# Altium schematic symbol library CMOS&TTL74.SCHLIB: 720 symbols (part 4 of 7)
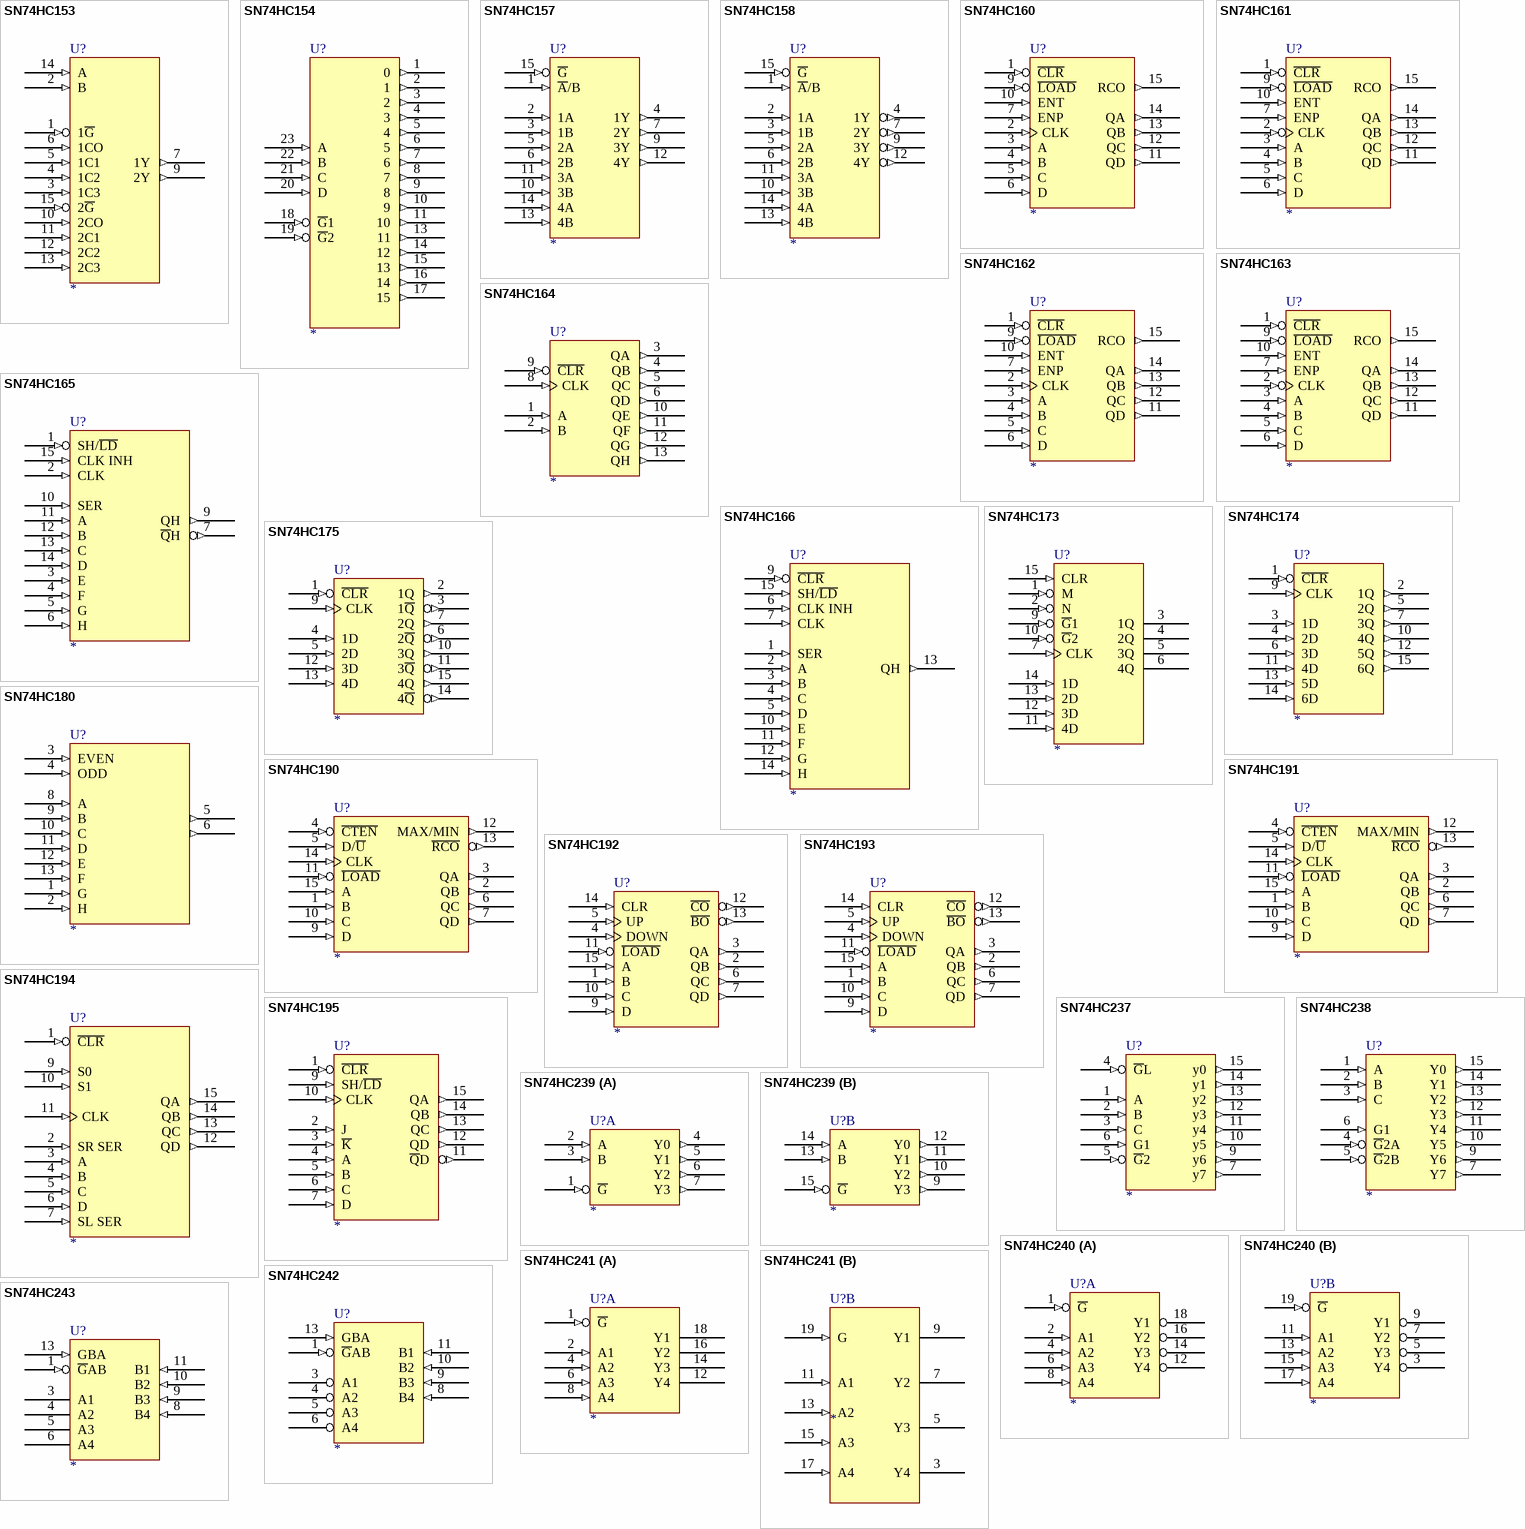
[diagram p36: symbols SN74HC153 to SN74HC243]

## SN74HC160
designator U?
SYN 4-BIT CNT
footprint SO16
footprint DIP-16
pins: 1 ~{CLR} (in), 2 CLK (in), 3 A (in), 4 B (in), 5 C (in), 6 D (in), 7 ENP (in), 8 GND (power) hidden to GND, 9 ~{LOAD} (in), 10 ENT (in), 11 QD (out), 12 QC (out), 13 QB (out), 14 QA (out), 15 RCO (out), 16 VCC (power) hidden to VCC
1 alternate drawing of the same symbol

## SN74HC161
designator U?
SYN 4-BIT CNT
footprint SO16
footprint DIP-16
pins: 1 ~{CLR} (in), 2 CLK (in), 3 A (in), 4 B (in), 5 C (in), 6 D (in), 7 ENP (in), 8 GND (power) hidden to GND, 9 ~{LOAD} (in), 10 ENT (in), 11 QD (out), 12 QC (out), 13 QB (out), 14 QA (out), 15 RCO (out), 16 VCC (power) hidden to VCC
1 alternate drawing of the same symbol

## SN74HC162
designator U?
SYN 4-BIT CNT
footprint SO16
footprint DIP-16
pins: 1 ~{CLR} (in), 2 CLK (in), 3 A (in), 4 B (in), 5 C (in), 6 D (in), 7 ENP (in), 8 GND (power) hidden to GND, 9 ~{LOAD} (in), 10 ENT (in), 11 QD (out), 12 QC (out), 13 QB (out), 14 QA (out), 15 RCO (out), 16 VCC (power) hidden to VCC
1 alternate drawing of the same symbol

## SN74HC163
designator U?
SYN 4-BIT CNT
footprint SO16
footprint DIP-16
pins: 1 ~{CLR} (in), 2 CLK (in), 3 A (in), 4 B (in), 5 C (in), 6 D (in), 7 ENP (in), 8 GND (power) hidden to GND, 9 ~{LOAD} (in), 10 ENT (in), 11 QD (out), 12 QC (out), 13 QB (out), 14 QA (out), 15 RCO (out), 16 VCC (power) hidden to VCC
1 alternate drawing of the same symbol

## SN74HC164
designator U?
8-BIT PALL SERI SFT REG
footprint DIP-14
pins: 1 A (in), 2 B (in), 3 QA (out), 4 QB (out), 5 QC (out), 6 QD (out), 7 GND (power) hidden to GND, 8 CLK (in), 9 ~{CLR} (in), 10 QE (out), 11 QF (out), 12 QG (out), 13 QH (out), 14 VCC (power) hidden to VCC
1 alternate drawing of the same symbol

## SN74HC165
designator U?
PALL LOAD 8-BIT SFT REG
footprint SO16
footprint DIP-16
pins: 1 SH/~{LD} (in), 2 CLK (in), 3 E (in), 4 F (in), 5 G (in), 6 H (in), 7 ~{Q}H (out), 8 GND (power) hidden to GND, 9 QH (out), 10 SER (in), 11 A (in), 12 B (in), 13 C (in), 14 D (in), 15 CLK INH (in), 16 VCC (power) hidden to VCC
1 alternate drawing of the same symbol

## SN74HC166
designator U?
PALL LOAD 8-BIT SFT REG
footprint SO16
footprint DIP-16
pins: 1 SER (in), 2 A (in), 3 B (in), 4 C (in), 5 D (in), 6 CLK INH (in), 7 CLK (in), 8 GND (power) hidden to GND, 9 ~{CLR} (in), 10 E (in), 11 F (in), 12 G (in), 13 QH (out), 14 H (in), 15 SH/~{LD} (in), 16 VCC (power) hidden to VCC
1 alternate drawing of the same symbol

## SN74HC173
designator U?
4-BIT D-TYPE REG 3SO
footprint SO16
footprint DIP-16
pins: 1 M (in), 2 N (in), 3 1Q (hiz), 4 2Q (hiz), 5 3Q (hiz), 6 4Q (hiz), 7 CLK (in), 8 GND (power) hidden to GND, 9 ~{G}1 (in), 10 ~{G}2 (in), 11 4D (in), 12 3D (in), 13 2D (in), 14 1D (in), 15 CLR (in), 16 VCC (power) hidden to VCC
1 alternate drawing of the same symbol

## SN74HC174
designator U?
HEX D-TYPE FF CR
footprint SO16
footprint DIP-16
pins: 1 ~{CLR} (in), 2 1Q (out), 3 1D (in), 4 2D (in), 5 2Q (out), 6 3D (in), 7 3Q (out), 8 GND (power) hidden to GND, 9 CLK (in), 10 4Q (out), 11 4D (in), 12 5Q (out), 13 5D (in), 14 6D (in), 15 6Q (out), 16 VCC (power) hidden to VCC
1 alternate drawing of the same symbol

## SN74HC175
designator U?
QUAD D-TYPE FF CR
footprint SO16
footprint DIP-16
pins: 1 ~{CLR} (in), 2 1Q (out), 3 1~{Q} (out), 4 1D (in), 5 2D (in), 6 2~{Q} (out), 7 2Q (out), 8 GND (power) hidden to GND, 9 CLK (in), 10 3Q (out), 11 3~{Q} (out), 12 3D (in), 13 4D (in), 14 4~{Q} (out), 15 4Q (out), 16 VCC (power) hidden to VCC
1 alternate drawing of the same symbol

## SN74HC180
designator U?
9-BIT PARITY GNR/CHKR
footprint SO14
footprint DIP-14
pins: 1 G (in), 2 H (in), 3 EVEN (in), 4 ODD (in), 5 (out), 6 (out), 7 GND (power) hidden to GND, 8 A (in), 9 B (in), 10 C (in), 11 D (in), 12 E (in), 13 F (in), 14 VCC (power) hidden to VCC
1 alternate drawing of the same symbol

## SN74HC190
designator U?
SYN UP/DOWN CNT DOWN/UP MODE CONTTOL
footprint SO16
footprint DIP-16
pins: 1 B (in), 2 QB (out), 3 QA (out), 4 ~{CTEN} (in), 5 D/~{U} (in), 6 QC (out), 7 QD (out), 8 GND (power) hidden to GND, 9 D (in), 10 C (in), 11 ~{LOAD} (in), 12 MAX/MIN (out), 13 ~{RCO} (out), 14 CLK (in), 15 A (in), 16 VCC (power) hidden to VCC
1 alternate drawing of the same symbol

## SN74HC191
designator U?
SYN UP/DOWN CNT DOWN/UP MODE CONTTOL
footprint SO16
footprint DIP-16
pins: 1 B (in), 2 QB (out), 3 QA (out), 4 ~{CTEN} (in), 5 D/~{U} (in), 6 QC (out), 7 QD (out), 8 GND (power) hidden to GND, 9 D (in), 10 C (in), 11 ~{LOAD} (in), 12 MAX/MIN (out), 13 ~{RCO} (out), 14 CLK (in), 15 A (in), 16 VCC (power) hidden to VCC
1 alternate drawing of the same symbol

## SN74HC192
designator U?
SYN 4-BIT UP/DOWN CNT DUAL CLK CR
footprint SO16
footprint DIP-16
pins: 1 B (in), 2 QB (out), 3 QA (out), 4 DOWN (in), 5 UP (in), 6 QC (out), 7 QD (out), 8 GND (power) hidden to GND, 9 D (in), 10 C (in), 11 ~{LOAD} (in), 12 ~{CO} (out), 13 ~{BO} (out), 14 CLR (in), 15 A (in), 16 VCC (power) hidden to VCC
1 alternate drawing of the same symbol

## SN74HC193
designator U?
SYN 4-BIT UP/DOWN CNT DUAL CLK CR
footprint SO16
footprint DIP-16
pins: 1 B (in), 2 QB (out), 3 QA (out), 4 DOWN (in), 5 UP (in), 6 QC (out), 7 QD (out), 8 GND (power) hidden to GND, 9 D (in), 10 C (in), 11 ~{LOAD} (in), 12 ~{CO} (out), 13 ~{BO} (out), 14 CLR (in), 15 A (in), 16 VCC (power) hidden to VCC
1 alternate drawing of the same symbol

## SN74HC194
designator U?
4-BIT BIDIRECTIONAL UNIVERSAL SFT REG
footprint DIP-16
pins: 1 ~{CLR} (in), 2 SR SER (in), 3 A (in), 4 B (in), 5 C (in), 6 D (in), 7 SL SER (in), 8 GND (power) hidden to GND, 9 S0 (in), 10 S1 (in), 11 CLK (in), 12 QD (out), 13 QC (out), 14 QB (out), 15 QA (out), 16 VCC (power) hidden to VCC
1 alternate drawing of the same symbol

## SN74HC195
designator U?
4-BIT PARALLEL ACCESS SFT REG
footprint DIP-16
pins: 1 ~{CLR} (in), 2 J (in), 3 ~{K} (in), 4 A (in), 5 B (in), 6 C (in), 7 D (in), 8 GND (power) hidden to GND, 9 SH/~{LD} (in), 10 CLK (in), 11 ~{Q}D (out), 12 QD (out), 13 QC (out), 14 QB (out), 15 QA (out), 16 VCC (power) hidden to VCC
1 alternate drawing of the same symbol

## SN74HC237
designator U?
3-8LINE DEC/DEMUL ADDRESS LCH
footprint SO16
footprint DIP-16
pins: 1 A (in), 2 B (in), 3 C (in), 4 ~{G}L (in), 5 ~{G}2 (in), 6 G1 (in), 7 y7 (out), 8 GND (power) hidden to GND, 9 y6 (out), 10 y5 (out), 11 y4 (out), 12 y3 (out), 13 y2 (out), 14 y1 (out), 15 y0 (out), 16 VCC (power) hidden to VCC
1 alternate drawing of the same symbol

## SN74HC238
designator U?
3-8LINE DEC/DEMUL
footprint SO16
footprint DIP-16
pins: 1 A (in), 2 B (in), 3 C (in), 4 ~{G}2A (in), 5 ~{G}2B (in), 6 G1 (in), 7 Y7 (out), 8 GND (power) hidden to GND, 9 Y6 (out), 10 Y5 (out), 11 Y4 (out), 12 Y3 (out), 13 Y2 (out), 14 Y1 (out), 15 Y0 (out), 16 VCC (power) hidden to VCC
1 alternate drawing of the same symbol

## SN74HC239
designator U?
DUAL 2-4LINE DEC/DEMULT
footprint SO16
footprint DIP-16
part A pins: 1 ~{G} (in), 2 A (in), 3 B (in), 4 Y0 (out), 5 Y1 (out), 6 Y2 (out), 7 Y3 (out), 8 GND (power) hidden to GND, 16 VCC (power) hidden to VCC
part B pins: 8 GND (power) hidden to GND, 9 Y3 (out), 10 Y2 (out), 11 Y1 (out), 12 Y0 (out), 13 B (in), 14 A (in), 15 ~{G} (in), 16 VCC (power) hidden to VCC
1 alternate drawing of the same symbol

## SN74HC240
designator U?
OCTAL BUF AND LIN DRV 3SO
footprint SO20W
footprint DIP-20
part A pins: 1 ~{G} (in), 2 A1 (in), 4 A2 (in), 6 A3 (in), 8 A4 (in), 10 GND (power) hidden to GND, 12 Y4 (hiz), 14 Y3 (hiz), 16 Y2 (hiz), 18 Y1 (hiz), 20 VCC (power) hidden to VCC
part B pins: 3 Y4 (hiz), 5 Y3 (hiz), 7 Y2 (hiz), 9 Y1 (hiz), 10 GND (power) hidden to GND, 11 A1 (in), 13 A2 (in), 15 A3 (in), 17 A4 (in), 19 ~{G} (in), 20 VCC (power) hidden to VCC
1 alternate drawing of the same symbol

## SN74HC241
designator U?
OCTAL BUF AND LIN DRV 3SO
footprint SO20W
footprint DIP-20
part A pins: 1 ~{G} (in), 2 A1 (in), 4 A2 (in), 6 A3 (in), 8 A4 (in), 10 GND (power) hidden to GND, 12 Y4 (hiz), 14 Y3 (hiz), 16 Y2 (hiz), 18 Y1 (hiz), 20 VCC (power) hidden to VCC
part B pins: 3 Y4 (hiz), 5 Y3 (hiz), 7 Y2 (hiz), 9 Y1 (hiz), 10 GND (power) hidden to GND, 11 A1 (in), 13 A2 (in), 15 A3 (in), 17 A4 (in), 19 G (in), 20 VCC (power) hidden to VCC
1 alternate drawing of the same symbol

## SN74HC242
designator U?
QUAD BUS TRANSCEIVER
footprint DIP-14
pins: 1 ~{G}AB (in), 3 A1 (hiz), 4 A2 (hiz), 5 A3 (hiz), 6 A4 (hiz), 7 GND (power) hidden to GND, 8 B4 (in), 9 B3 (in), 10 B2 (in), 11 B1 (in), 13 GBA (in), 14 VCC (power) hidden to VCC
1 alternate drawing of the same symbol

## SN74HC243
designator U?
QUAD BUS TRANSCEIVER
footprint DIP-14
pins: 1 ~{G}AB (in), 3 A1 (hiz), 4 A2 (hiz), 5 A3 (hiz), 6 A4 (hiz), 7 GND (power) hidden to GND, 8 B4 (in), 9 B3 (in), 10 B2 (in), 11 B1 (in), 13 GBA (in), 14 VCC (power) hidden to VCC
1 alternate drawing of the same symbol

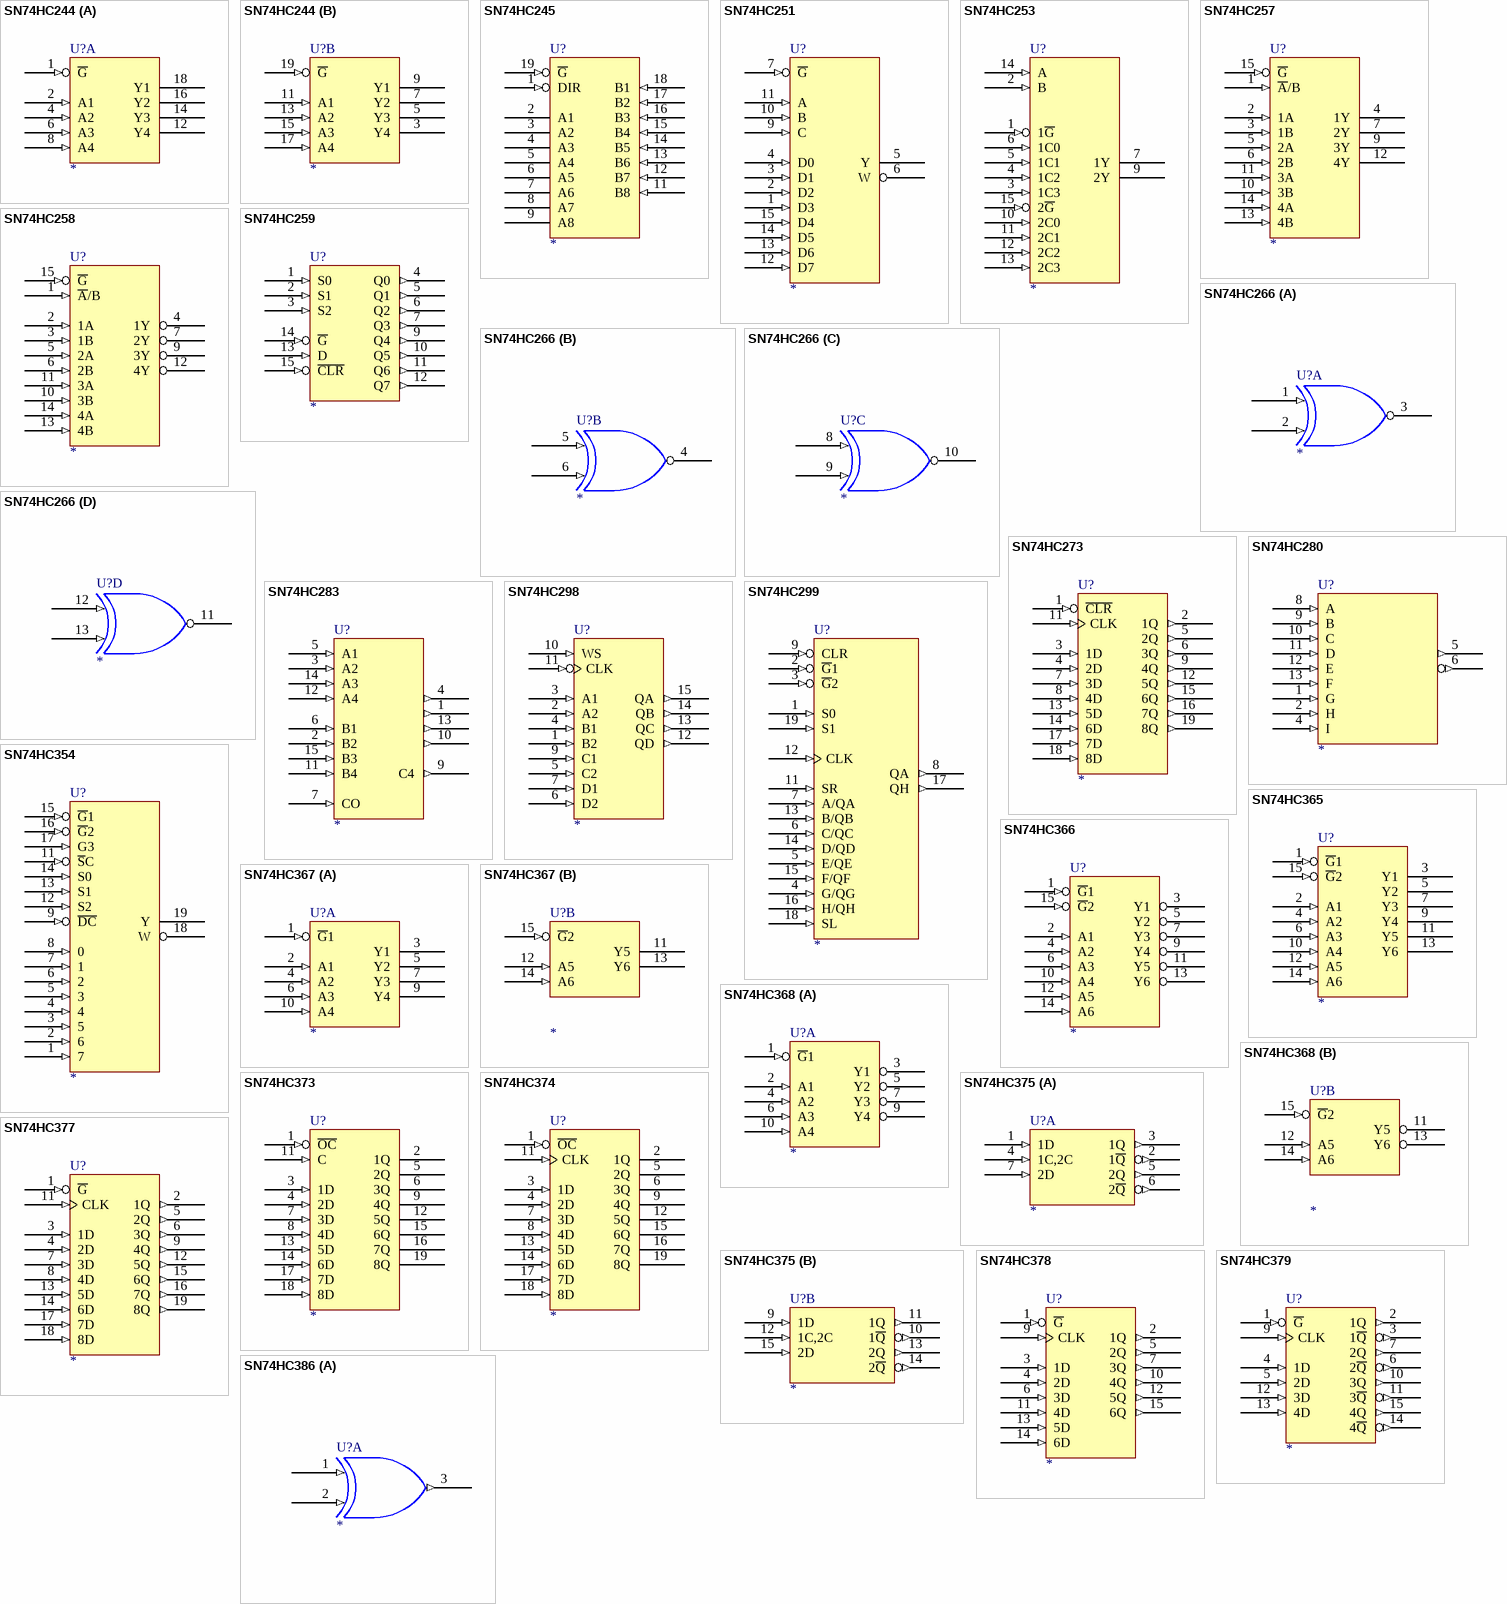
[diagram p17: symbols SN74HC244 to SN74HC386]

## SN74HC244
designator U?
OCTAL BUF AND LIN DRV 3SO
footprint SO20W
footprint DIP-20
part A pins: 1 ~{G} (in), 2 A1 (in), 4 A2 (in), 6 A3 (in), 8 A4 (in), 10 GND (power) hidden to GND, 12 Y4 (hiz), 14 Y3 (hiz), 16 Y2 (hiz), 18 Y1 (hiz), 20 VCC (power) hidden to VCC
part B pins: 3 Y4 (hiz), 5 Y3 (hiz), 7 Y2 (hiz), 9 Y1 (hiz), 10 GND (power) hidden to GND, 11 A1 (in), 13 A2 (in), 15 A3 (in), 17 A4 (in), 19 ~{G} (in), 20 VCC (power) hidden to VCC
1 alternate drawing of the same symbol

## SN74HC245
designator U?
QUAD BUS TRANSCEIVER 3SO
footprint SO20W
footprint DIP-20
pins: 1 DIR (in), 2 A1 (hiz), 3 A2 (hiz), 4 A3 (hiz), 5 A4 (hiz), 6 A5 (hiz), 7 A6 (hiz), 8 A7 (hiz), 9 A8 (hiz), 10 GND (power) hidden to GND, 11 B8 (in), 12 B7 (in), 13 B6 (in), 14 B5 (in), 15 B4 (in), 16 B3 (in), 17 B2 (in), 18 B1 (in), 19 ~{G} (in), 20 VCC (power) hidden to VCC
1 alternate drawing of the same symbol

## SN74HC251
designator U?
DATA SLCR/MUX 3SO
footprint SO16
footprint DIP-16
pins: 1 D3 (in), 2 D2 (in), 3 D1 (in), 4 D0 (in), 5 Y (hiz), 6 W (hiz), 7 ~{G} (in), 8 GND (power) hidden to GND, 9 C (in), 10 B (in), 11 A (in), 12 D7 (in), 13 D6 (in), 14 D5 (in), 15 D4 (in), 16 VCC (power) hidden to VCC
1 alternate drawing of the same symbol

## SN74HC253
designator U?
DUAL 4-1LINES DATA SLCR/MUX
footprint SO16
footprint DIP-16
pins: 1 1~{G} (in), 2 B (in), 3 1C3 (in), 4 1C2 (in), 5 1C1 (in), 6 1C0 (in), 7 1Y (hiz), 8 GND (power) hidden to GND, 9 2Y (hiz), 10 2C0 (in), 11 2C1 (in), 12 2C2 (in), 13 2C3 (in), 14 A (in), 15 2~{G} (in), 16 VCC (power) hidden to VCC
1 alternate drawing of the same symbol

## SN74HC257
designator U?
QUAD 2-1LINE DATA SLCR/MUX
footprint SO16
footprint DIP-16
pins: 1 ~{A}/B (in), 2 1A (in), 3 1B (in), 4 1Y (hiz), 5 2A (in), 6 2B (in), 7 2Y (hiz), 8 GND (power) hidden to GND, 9 3Y (hiz), 10 3B (in), 11 3A (in), 12 4Y (hiz), 13 4B (in), 14 4A (in), 15 ~{G} (in), 16 VCC (power) hidden to VCC
1 alternate drawing of the same symbol

## SN74HC258
designator U?
QUAD 2-1LINE DATA SLCR/MUX
footprint SO16
footprint DIP-16
pins: 1 ~{A}/B (in), 2 1A (in), 3 1B (in), 4 1Y (hiz), 5 2A (in), 6 2B (in), 7 2Y (hiz), 8 GND (power) hidden to GND, 9 3Y (hiz), 10 3B (in), 11 3A (in), 12 4Y (hiz), 13 4B (in), 14 4A (in), 15 ~{G} (in), 16 VCC (power) hidden to VCC
1 alternate drawing of the same symbol

## SN74HC259
designator U?
8-BIT ADDRESSABLE LCH
footprint SO16
footprint DIP-16
pins: 1 S0 (in), 2 S1 (in), 3 S2 (in), 4 Q0 (out), 5 Q1 (out), 6 Q2 (out), 7 Q3 (out), 8 GND (power) hidden to GND, 9 Q4 (out), 10 Q5 (out), 11 Q6 (out), 12 Q7 (out), 13 D (in), 14 ~{G} (in), 15 ~{CLR} (in), 16 VCC (power) hidden to VCC
1 alternate drawing of the same symbol

## SN74HC266
designator U?
QUAD 2-IN XOR  G OCO
footprint SO14
footprint DIP-14
part A pins: 1 (in), 2 (in), 3 (oc), 7 GND (power) hidden to GND, 14 VCC (power) hidden to VCC
part B pins: 4 (oc), 5 (in), 6 (in), 7 GND (power) hidden to GND, 14 VCC (power) hidden to VCC
part C pins: 7 GND (power) hidden to GND, 8 (in), 9 (in), 10 (oc), 14 VCC (power) hidden to VCC
part D pins: 7 GND (power) hidden to GND, 11 (oc), 12 (in), 13 (in), 14 VCC (power) hidden to VCC
1 alternate drawing of the same symbol

## SN74HC273
designator U?
OCTAL D-TYPE FF CR
footprint SO20W
footprint DIP-20
pins: 1 ~{CLR} (in), 2 1Q (out), 3 1D (in), 4 2D (in), 5 2Q (out), 6 3Q (out), 7 3D (in), 8 4D (in), 9 4Q (out), 10 GND (power) hidden to GND, 11 CLK (in), 12 5Q (out), 13 5D (in), 14 6D (in), 15 6Q (out), 16 7Q (out), 17 7D (in), 18 8D (in), 19 8Q (out), 20 VCC (power) hidden to VCC
1 alternate drawing of the same symbol

## SN74HC280
designator U?
9-BIT ODD/EVEN PARITY GNR/CHKR
footprint SO14
footprint DIP-14
pins: 1 G (in), 2 H (in), 4 I (in), 5 (out), 6 (out), 7 GND (power) hidden to GND, 8 A (in), 9 B (in), 10 C (in), 11 D (in), 12 E (in), 13 F (in), 14 VCC (power) hidden to VCC
1 alternate drawing of the same symbol

## SN74HC283
designator U?
4-BIT BIN ADD WITH FC
footprint SO16
footprint DIP-16
pins: 1 (out), 2 B2 (in), 3 A2 (in), 4 (out), 5 A1 (in), 6 B1 (in), 7 CO (in), 8 GND (power) hidden to GND, 9 C4 (out), 10 (out), 11 B4 (in), 12 A4 (in), 13 (out), 14 A3 (in), 15 B3 (in), 16 VCC (power) hidden to VCC
1 alternate drawing of the same symbol

## SN74HC298
designator U?
QUAD 2-IN MUX WITH STORAGE
footprint DIP-16
pins: 1 B2 (in), 2 A2 (in), 3 A1 (in), 4 B1 (in), 5 C2 (in), 6 D2 (in), 7 D1 (in), 8 GND (power) hidden to GND, 9 C1 (in), 10 WS (in), 11 CLK (in), 12 QD (out), 13 QC (out), 14 QB (out), 15 QA (out), 16 VCC (power) hidden to VCC
1 alternate drawing of the same symbol

## SN74HC299
designator U?
8-BIT UNIVERSAL SFT/STORAGE REG
footprint SO20W
footprint DIP-20
pins: 1 S0 (in), 2 ~{G}1 (in), 3 ~{G}2 (in), 4 G/QG (in), 5 E/QE (in), 6 C/QC (in), 7 A/QA (in), 8 QA (out), 9 CLR (in), 10 GND (power) hidden to GND, 11 SR (in), 12 CLK (in), 13 B/QB (in), 14 D/QD (in), 15 F/QF (in), 16 H/QH (in), 17 QH (out), 18 SL (in), 19 S1 (in), 20 VCC (power) hidden to VCC
1 alternate drawing of the same symbol

## SN74HC354
designator U?
8-1LINE DATA SLCR/MUX/REG
footprint SO20W
footprint DIP-20
pins: 1 7 (in), 2 6 (in), 3 5 (in), 4 (in), 5 3 (in), 6 2 (in), 7 1 (in), 8 0 (in), 9 ~{DC} (in), 10 GND (power) hidden to GND, 11 ~{S}C (in), 12 S2 (in), 13 S1 (in), 14 S0 (in), 15 ~{G}1 (in), 16 ~{G}2 (in), 17 G3 (in), 18 W (hiz), 19 Y (hiz), 20 VCC (power) hidden to VCC
1 alternate drawing of the same symbol

## SN74HC365
designator U?
HEX BUS DRV 3SO
footprint SO16
footprint DIP-16
pins: 1 ~{G}1 (in), 2 A1 (in), 3 Y1 (hiz), 4 A2 (in), 5 Y2 (hiz), 6 A3 (in), 7 Y3 (hiz), 8 GND (power) hidden to GND, 9 Y4 (hiz), 10 A4 (in), 11 Y5 (hiz), 12 A5 (in), 13 Y6 (hiz), 14 A6 (in), 15 ~{G}2 (in), 16 VCC (power) hidden to VCC
1 alternate drawing of the same symbol

## SN74HC366
designator U?
HEX BUS DRV 3SO
footprint SO16
footprint DIP-16
pins: 1 ~{G}1 (in), 2 A1 (in), 3 Y1 (hiz), 4 A2 (in), 5 Y2 (hiz), 6 A3 (in), 7 Y3 (hiz), 8 GND (power) hidden to GND, 9 Y4 (hiz), 10 A4 (in), 11 Y5 (hiz), 12 A5 (in), 13 Y6 (hiz), 14 A6 (in), 15 ~{G}2 (in), 16 VCC (power) hidden to VCC
1 alternate drawing of the same symbol

## SN74HC367
designator U?
HEX BUS DRV 3SO
footprint SO16
footprint DIP-16
part A pins: 1 ~{G}1 (in), 2 A1 (in), 3 Y1 (hiz), 4 A2 (in), 5 Y2 (hiz), 6 A3 (in), 7 Y3 (hiz), 8 GND (power) hidden to GND, 9 Y4 (hiz), 10 A4 (in), 16 VCC (power) hidden to VCC
part B pins: 8 GND (power) hidden to GND, 11 Y5 (hiz), 12 A5 (in), 13 Y6 (hiz), 14 A6 (in), 15 ~{G}2 (in), 16 VCC (power) hidden to VCC
1 alternate drawing of the same symbol

## SN74HC368
designator U?
HEX BUS DRV 3SO
footprint SO16
footprint DIP-16
part A pins: 1 ~{G}1 (in), 2 A1 (in), 3 Y1 (hiz), 4 A2 (in), 5 Y2 (hiz), 6 A3 (in), 7 Y3 (hiz), 8 GND (power) hidden to GND, 9 Y4 (hiz), 10 A4 (in), 16 VCC (power) hidden to VCC
part B pins: 8 GND (power) hidden to GND, 11 Y5 (hiz), 12 A5 (in), 13 Y6 (hiz), 14 A6 (in), 15 ~{G}2 (in), 16 VCC (power) hidden to VCC
1 alternate drawing of the same symbol

## SN74HC373
designator U?
OCTAL TRANSPARENT LCH
footprint SO20W
footprint DIP-20
pins: 1 ~{OC} (in), 2 1Q (hiz), 3 1D (in), 4 2D (in), 5 2Q (hiz), 6 3Q (hiz), 7 3D (in), 8 4D (in), 9 4Q (hiz), 10 GND (power) hidden to GND, 11 C (in), 12 5Q (hiz), 13 5D (in), 14 6D (in), 15 6Q (hiz), 16 7Q (hiz), 17 7D (in), 18 8D (in), 19 8Q (hiz), 20 VCC (power) hidden to VCC
1 alternate drawing of the same symbol

## SN74HC374
designator U?
OCTAL  D-TYPE EDGE-TRIGGERED FF 3SO
footprint SO20W
footprint DIP-20
pins: 1 ~{OC} (in), 2 1Q (hiz), 3 1D (in), 4 2D (in), 5 2Q (hiz), 6 3Q (hiz), 7 3D (in), 8 4D (in), 9 4Q (hiz), 10 GND (power) hidden to GND, 11 CLK (in), 12 5Q (hiz), 13 5D (in), 14 6D (in), 15 6Q (hiz), 16 7Q (hiz), 17 7D (in), 18 8D (in), 19 8Q (hiz), 20 VCC (power) hidden to VCC
1 alternate drawing of the same symbol

## SN74HC375
designator U?
4-BIT BISTABLE LCH
footprint SO16
footprint DIP-16
part A pins: 1 1D (in), 2 1~{Q} (out), 3 1Q (out), 4 1C,2C (in), 5 2Q (out), 6 2~{Q} (out), 7 2D (in), 8 GND (power) hidden to GND, 16 VCC (power) hidden to VCC
part B pins: 8 GND (power) hidden to GND, 9 1D (in), 10 1~{Q} (out), 11 1Q (out), 12 1C,2C (in), 13 2Q (out), 14 2~{Q} (out), 15 2D (in), 16 VCC (power) hidden to VCC
1 alternate drawing of the same symbol

## SN74HC377
designator U?
OCTAL D-TYPE FF WITH ENABLE
footprint SO20W
footprint DIP-20
pins: 1 ~{G} (in), 2 1Q (out), 3 1D (in), 4 2D (in), 5 2Q (out), 6 3Q (out), 7 3D (in), 8 4D (in), 9 4Q (out), 10 GND (power) hidden to GND, 11 CLK (in), 12 5Q (out), 13 5D (in), 14 6D (in), 15 6Q (out), 16 7Q (out), 17 7D (in), 18 8D (in), 19 8Q (out), 20 VCC (power) hidden to VCC
1 alternate drawing of the same symbol

## SN74HC378
designator U?
HEX D-TYPE FF WITH ENABLE
footprint SO16
footprint DIP-16
pins: 1 ~{G} (in), 2 1Q (out), 3 1D (in), 4 2D (in), 5 2Q (out), 6 3D (in), 7 3Q (out), 8 GND (power) hidden to GND, 9 CLK (in), 10 4Q (out), 11 4D (in), 12 5Q (out), 13 5D (in), 14 6D (in), 15 6Q (out), 16 VCC (power) hidden to VCC
1 alternate drawing of the same symbol

## SN74HC379
designator U?
QUAD D-TYPE FF WITH ENABLE
footprint SO16
footprint DIP-16
pins: 1 ~{G} (in), 2 1Q (out), 3 1~{Q} (out), 4 1D (in), 5 2D (in), 6 2~{Q} (out), 7 2Q (out), 8 GND (power) hidden to GND, 9 CLK (in), 10 3Q (out), 11 3~{Q} (out), 12 3D (in), 13 4D (in), 14 4~{Q} (out), 15 4Q (out), 16 VCC (power) hidden to VCC
1 alternate drawing of the same symbol

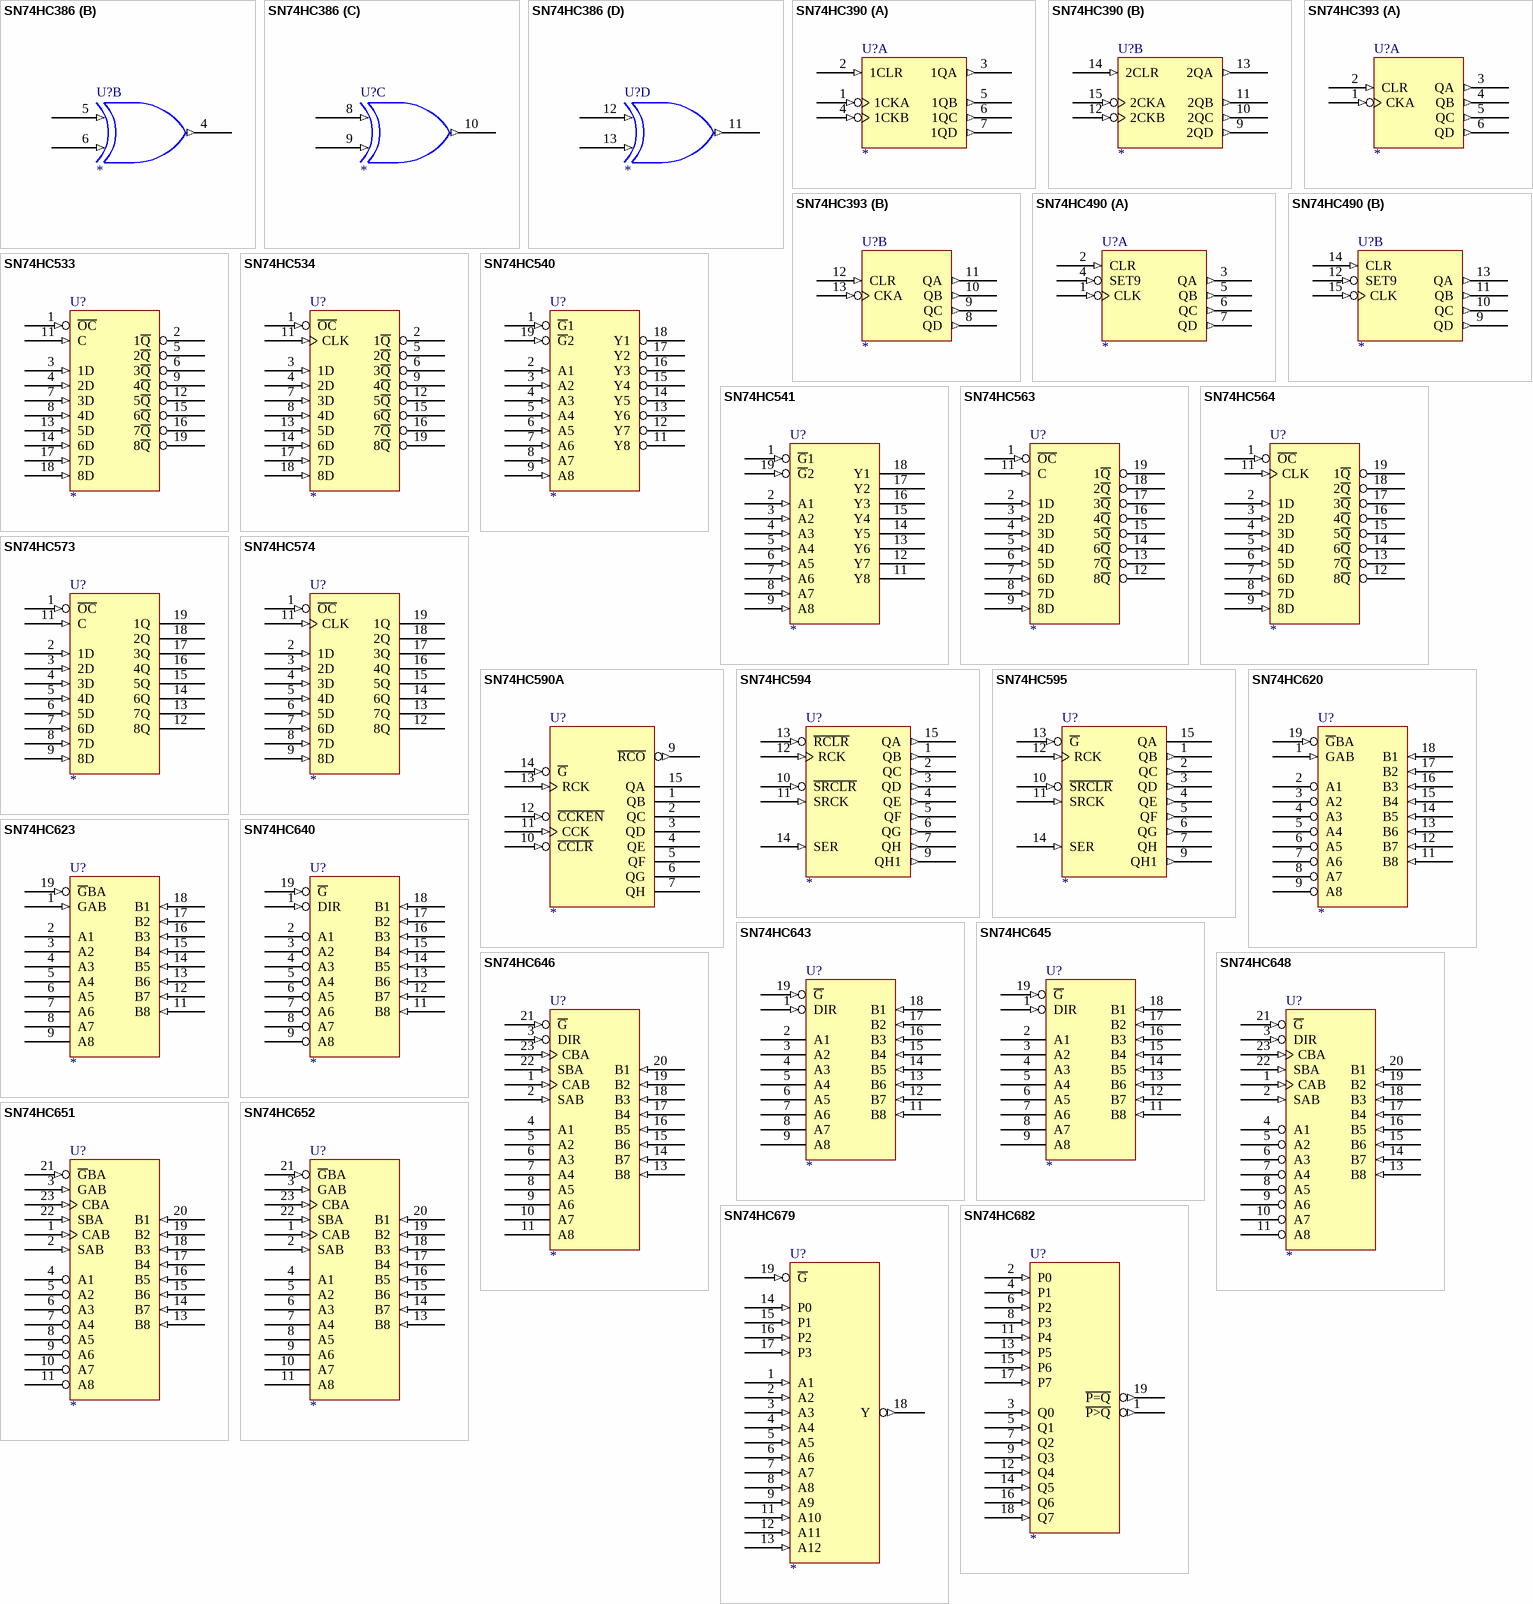
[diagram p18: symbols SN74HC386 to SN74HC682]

## SN74HC386
designator U?
QUAD 2-IN XOR
footprint SO14
footprint DIP-14
part A pins: 1 (in), 2 (in), 3 (out), 7 GND (power) hidden to GND, 14 VCC (power) hidden to VCC
part B pins: 4 (out), 5 (in), 6 (in), 7 GND (power) hidden to GND, 14 VCC (power) hidden to VCC
part C pins: 7 GND (power) hidden to GND, 8 (in), 9 (in), 10 (out), 14 VCC (power) hidden to VCC
part D pins: 7 GND (power) hidden to GND, 11 (out), 12 (in), 13 (in), 14 VCC (power) hidden to VCC
1 alternate drawing of the same symbol

## SN74HC390
designator U?
DUAL 4-BIT AND BIN CNT
footprint SO16
footprint DIP-16
part A pins: 1 1CKA (in), 2 1CLR (in), 3 1QA (out), 4 1CKB (in), 5 1QB (out), 6 1QC (out), 7 1QD (out), 8 GND (power) hidden to GND, 16 VCC (power) hidden to VCC
part B pins: 8 GND (power) hidden to GND, 9 2QD (out), 10 2QC (out), 11 2QB (out), 12 2CKB (in), 13 2QA (out), 14 2CLR (in), 15 2CKA (in), 16 VCC (power) hidden to VCC
1 alternate drawing of the same symbol

## SN74HC393
designator U?
DUAL 4-BIT AND BIN CNT
footprint DIP-14
part A pins: 1 CKA (in), 2 CLR (in), 3 QA (out), 4 QB (out), 5 QC (out), 6 QD (out), 7 GND (power) hidden to GND, 14 VCC (power) hidden to VCC
part B pins: 7 GND (power) hidden to GND, 8 QD (out), 9 QC (out), 10 QB (out), 11 QA (out), 12 CLR (in), 13 CKA (in), 14 VCC (power) hidden to VCC
1 alternate drawing of the same symbol

## SN74HC490
designator U?
DUAL 4-BIT AND BIN CNT
footprint DIP-16
part A pins: 1 CLK (in), 2 CLR (in), 3 QA (out), 4 SET9 (in), 5 QB (out), 6 QC (out), 7 QD (out), 8 GND (power) hidden to GND, 16 VCC (power) hidden to VCC
part B pins: 8 GND (power) hidden to GND, 9 QD (out), 10 QC (out), 11 QB (out), 12 SET9 (in), 13 QA (out), 14 CLR (in), 15 CLK (in), 16 VCC (power) hidden to VCC
1 alternate drawing of the same symbol

## SN74HC533
designator U?
OCTAL D-TYPE TRANSPARENT LCH 3SO
footprint SO20W
footprint DIP-20
pins: 1 ~{OC} (in), 2 1~{Q} (hiz), 3 1D (in), 4 2D (in), 5 2~{Q} (hiz), 6 3~{Q} (hiz), 7 3D (in), 8 4D (in), 9 4~{Q} (hiz), 10 GND (power) hidden to GND, 11 C (in), 12 5~{Q} (hiz), 13 5D (in), 14 6D (in), 15 6~{Q} (hiz), 16 7~{Q} (hiz), 17 7D (in), 18 8D (in), 19 8~{Q} (hiz), 20 VCC (power) hidden to VCC
1 alternate drawing of the same symbol

## SN74HC534
designator U?
OCTAL TRANSPARENT LCH
footprint SO20W
footprint DIP-20
pins: 1 ~{OC} (in), 2 1~{Q} (hiz), 3 1D (in), 4 2D (in), 5 2~{Q} (hiz), 6 3~{Q} (hiz), 7 3D (in), 8 4D (in), 9 4~{Q} (hiz), 10 GND (power) hidden to GND, 11 CLK (in), 12 5~{Q} (hiz), 13 5D (in), 14 6D (in), 15 6~{Q} (hiz), 16 7~{Q} (hiz), 17 7D (in), 18 8D (in), 19 8~{Q} (hiz), 20 VCC (power) hidden to VCC
1 alternate drawing of the same symbol

## SN74HC540
designator U?
OCTAL BUF AND LINE DRV 3SO
footprint SO20W
footprint DIP-20
pins: 1 ~{G}1 (in), 2 A1 (in), 3 A2 (in), 4 A3 (in), 5 A4 (in), 6 A5 (in), 7 A6 (in), 8 A7 (in), 9 A8 (in), 10 GND (power) hidden to GND, 11 Y8 (hiz), 12 Y7 (hiz), 13 Y6 (hiz), 14 Y5 (hiz), 15 Y4 (hiz), 16 Y3 (hiz), 17 Y2 (hiz), 18 Y1 (hiz), 19 ~{G}2 (in), 20 VCC (power) hidden to VCC
1 alternate drawing of the same symbol

## SN74HC541
designator U?
OCTAL BUF AND LINE DRV 3SO
footprint SO20W
footprint DIP-20
pins: 1 ~{G}1 (in), 2 A1 (in), 3 A2 (in), 4 A3 (in), 5 A4 (in), 6 A5 (in), 7 A6 (in), 8 A7 (in), 9 A8 (in), 10 GND (power) hidden to GND, 11 Y8 (hiz), 12 Y7 (hiz), 13 Y6 (hiz), 14 Y5 (hiz), 15 Y4 (hiz), 16 Y3 (hiz), 17 Y2 (hiz), 18 Y1 (hiz), 19 ~{G}2 (in), 20 VCC (power) hidden to VCC
1 alternate drawing of the same symbol

## SN74HC563
designator U?
OCTAL D-TYPE TRANSPARENT LCH 3SO
footprint SO20W
footprint DIP-20
pins: 1 ~{OC} (in), 2 1D (in), 3 2D (in), 4 3D (in), 5 4D (in), 6 5D (in), 7 6D (in), 8 7D (in), 9 8D (in), 10 GND (power) hidden to GND, 11 C (in), 12 8~{Q} (hiz), 13 7~{Q} (hiz), 14 6~{Q} (hiz), 15 5~{Q} (hiz), 16 4~{Q} (hiz), 17 3~{Q} (hiz), 18 2~{Q} (hiz), 19 1~{Q} (hiz), 20 VCC (power) hidden to VCC
1 alternate drawing of the same symbol

## SN74HC564
designator U?
OCTAL D-TYPE EDGE-TRIGGERED FF 3SO
footprint SO20W
footprint DIP-20
pins: 1 ~{OC} (in), 2 1D (in), 3 2D (in), 4 3D (in), 5 4D (in), 6 5D (in), 7 6D (in), 8 7D (in), 9 8D (in), 10 GND (power) hidden to GND, 11 CLK (in), 12 8~{Q} (hiz), 13 7~{Q} (hiz), 14 6~{Q} (hiz), 15 5~{Q} (hiz), 16 4~{Q} (hiz), 17 3~{Q} (hiz), 18 2~{Q} (hiz), 19 1~{Q} (hiz), 20 VCC (power) hidden to VCC
1 alternate drawing of the same symbol

## SN74HC573
designator U?
OCTAL D-TYPE TRANSPARENT LCH 3SO
footprint SO20W
footprint DIP-20
pins: 1 ~{OC} (in), 2 1D (in), 3 2D (in), 4 3D (in), 5 4D (in), 6 5D (in), 7 6D (in), 8 7D (in), 9 8D (in), 10 GND (power) hidden to GND, 11 C (in), 12 8Q (hiz), 13 7Q (hiz), 14 6Q (hiz), 15 5Q (hiz), 16 4Q (hiz), 17 3Q (hiz), 18 2Q (hiz), 19 1Q (hiz), 20 VCC (power) hidden to VCC
1 alternate drawing of the same symbol

## SN74HC574
designator U?
OCTAL D-TYPE EDGE-TRIGGERED FF 3SO
footprint SO20W
footprint DIP-20
pins: 1 ~{OC} (in), 2 1D (in), 3 2D (in), 4 3D (in), 5 4D (in), 6 5D (in), 7 6D (in), 8 7D (in), 9 8D (in), 10 GND (power) hidden to GND, 11 CLK (in), 12 8Q (hiz), 13 7Q (hiz), 14 6Q (hiz), 15 5Q (hiz), 16 4Q (hiz), 17 3Q (hiz), 18 2Q (hiz), 19 1Q (hiz), 20 VCC (power) hidden to VCC
1 alternate drawing of the same symbol

## SN74HC590A
designator U?
8-BIT BIN CNT WITH OUTPUT REGISTERS
footprint SO16W
footprint DIP-16
pins: 1 QB (hiz), 2 QC (hiz), 3 QD (hiz), 4 QE (hiz), 5 QF (hiz), 6 QG (hiz), 7 QH (hiz), 8 GND (power) hidden to GND, 9 ~{RCO} (out), 10 ~{CCLR} (in), 11 CCK (in), 12 ~{CCKEN} (in), 13 RCK (in), 14 ~{G} (in), 15 QA (hiz), 16 VCC (power) hidden to VCC
1 alternate drawing of the same symbol

## SN74HC594
designator U?
8-BIT SFT REG WIRTH OUTPUT LCH
footprint SO16
footprint DIP-16
pins: 1 QB (out), 2 QC (out), 3 QD (out), 4 QE (out), 5 QF (out), 6 QG (out), 7 QH (out), 8 GND (power) hidden to GND, 9 QH1 (out), 10 ~{SRCLR} (in), 11 SRCK (in), 12 RCK (in), 13 ~{RCLR} (in), 14 SER (in), 15 QA (out), 16 VCC (power) hidden to VCC
1 alternate drawing of the same symbol

## SN74HC595
designator U?
8-BIT SFT REG WIRTH OUTPUT LCH
footprint SO16
footprint DIP-16
pins: 1 QB (out), 2 QC (out), 3 QD (out), 4 QE (out), 5 QF (out), 6 QG (out), 7 QH (hiz), 8 GND (power) hidden to GND, 9 QH1 (out), 10 ~{SRCLR} (in), 11 SRCK (in), 12 RCK (in), 13 ~{G} (in), 14 SER (in), 15 QA (hiz), 16 VCC (power) hidden to VCC
1 alternate drawing of the same symbol

## SN74HC620
designator U?
OCTAL BUS TRANCEIVER
footprint SO20W
footprint DIP-20
pins: 1 GAB (in), 2 A1 (hiz), 3 A2 (hiz), 4 A3 (hiz), 5 A4 (hiz), 6 A5 (hiz), 7 A6 (hiz), 8 A7 (hiz), 9 A8 (hiz), 10 GND (power) hidden to GND, 11 B8 (in), 12 B7 (in), 13 B6 (in), 14 B5 (in), 15 B4 (in), 16 B3 (in), 17 B2 (in), 18 B1 (in), 19 ~{G}BA (in), 20 VCC (power) hidden to VCC
1 alternate drawing of the same symbol

## SN74HC623
designator U?
OCTAL BUS TRANCEIVER
footprint SO20W
footprint DIP-20
pins: 1 GAB (in), 2 A1 (hiz), 3 A2 (hiz), 4 A3 (hiz), 5 A4 (hiz), 6 A5 (hiz), 7 A6 (hiz), 8 A7 (hiz), 9 A8 (hiz), 10 GND (power) hidden to GND, 11 B8 (in), 12 B7 (in), 13 B6 (in), 14 B5 (in), 15 B4 (in), 16 B3 (in), 17 B2 (in), 18 B1 (in), 19 ~{G}BA (in), 20 VCC (power) hidden to VCC
1 alternate drawing of the same symbol

## SN74HC640
designator U?
OCTAL BUS TRANCEIVER
footprint SO20W
footprint DIP-20
pins: 1 DIR (in), 2 A1 (hiz), 3 A2 (hiz), 4 A3 (hiz), 5 A4 (hiz), 6 A5 (hiz), 7 A6 (hiz), 8 A7 (hiz), 9 A8 (hiz), 10 GND (power) hidden to GND, 11 B8 (in), 12 B7 (in), 13 B6 (in), 14 B5 (in), 15 B4 (in), 16 B3 (in), 17 B2 (in), 18 B1 (in), 19 ~{G} (in), 20 VCC (power) hidden to VCC
1 alternate drawing of the same symbol

## SN74HC643
designator U?
OCTAL BUS TRANCEIVER
footprint SO20W
footprint DIP-20
pins: 1 DIR (in), 2 A1 (hiz), 3 A2 (hiz), 4 A3 (hiz), 5 A4 (hiz), 6 A5 (hiz), 7 A6 (hiz), 8 A7 (hiz), 9 A8 (hiz), 10 GND (power) hidden to GND, 11 B8 (in), 12 B7 (in), 13 B6 (in), 14 B5 (in), 15 B4 (in), 16 B3 (in), 17 B2 (in), 18 B1 (in), 19 ~{G} (in), 20 VCC (power) hidden to VCC
1 alternate drawing of the same symbol

## SN74HC645
designator U?
OCTAL BUS TRANCEIVER
footprint SO20W
footprint DIP-20
pins: 1 DIR (in), 2 A1 (hiz), 3 A2 (hiz), 4 A3 (hiz), 5 A4 (hiz), 6 A5 (hiz), 7 A6 (hiz), 8 A7 (hiz), 9 A8 (hiz), 10 GND (power) hidden to GND, 11 B8 (in), 12 B7 (in), 13 B6 (in), 14 B5 (in), 15 B4 (in), 16 B3 (in), 17 B2 (in), 18 B1 (in), 19 ~{G} (in), 20 VCC (power) hidden to VCC
1 alternate drawing of the same symbol

## SN74HC646
designator U?
OCTAL BUS TRANCEIVER AND REG
footprint SO24W
footprint DIP-24
pins: 1 CAB (in), 2 SAB (in), 3 DIR (in), 4 A1 (hiz), 5 A2 (hiz), 6 A3 (hiz), 7 A4 (hiz), 8 A5 (hiz), 9 A6 (hiz), 10 A7 (hiz), 11 A8 (hiz), 12 GND (power) hidden to GND, 13 B8 (in), 14 B7 (in), 15 B6 (in), 16 B5 (in), 17 B4 (in), 18 B3 (in), 19 B2 (in), 20 B1 (in), 21 ~{G} (in), 22 SBA (in), 23 CBA (in), 24 VCC (power) hidden to VCC
1 alternate drawing of the same symbol

## SN74HC648
designator U?
OCTAL BUS TRANCEIVER AND REG
footprint SO24W
footprint DIP-24
pins: 1 CAB (in), 2 SAB (in), 3 DIR (in), 4 A1 (hiz), 5 A2 (hiz), 6 A3 (hiz), 7 A4 (hiz), 8 A5 (hiz), 9 A6 (hiz), 10 A7 (hiz), 11 A8 (hiz), 12 GND (power) hidden to GND, 13 B8 (in), 14 B7 (in), 15 B6 (in), 16 B5 (in), 17 B4 (in), 18 B3 (in), 19 B2 (in), 20 B1 (in), 21 ~{G} (in), 22 SBA (in), 23 CBA (in), 24 VCC (power) hidden to VCC
1 alternate drawing of the same symbol

## SN74HC651
designator U?
OCTAL BUS TRANCEIVER AND REG
footprint SO24W
footprint DIP-24
pins: 1 CAB (in), 2 SAB (in), 3 GAB (in), 4 A1 (hiz), 5 A2 (hiz), 6 A3 (hiz), 7 A4 (hiz), 8 A5 (hiz), 9 A6 (hiz), 10 A7 (hiz), 11 A8 (hiz), 12 GND (power) hidden to GND, 13 B8 (in), 14 B7 (in), 15 B6 (in), 16 B5 (in), 17 B4 (in), 18 B3 (in), 19 B2 (in), 20 B1 (in), 21 ~{G}BA (in), 22 SBA (in), 23 CBA (in), 24 VCC (power) hidden to VCC
1 alternate drawing of the same symbol

## SN74HC652
designator U?
OCTAL BUS TRANCEIVER AND REG
footprint SO24W
footprint DIP-24
pins: 1 CAB (in), 2 SAB (in), 3 GAB (in), 4 A1 (hiz), 5 A2 (hiz), 6 A3 (hiz), 7 A4 (hiz), 8 A5 (hiz), 9 A6 (hiz), 10 A7 (hiz), 11 A8 (hiz), 12 GND (power) hidden to GND, 13 B8 (in), 14 B7 (in), 15 B6 (in), 16 B5 (in), 17 B4 (in), 18 B3 (in), 19 B2 (in), 20 B1 (in), 21 ~{G}BA (in), 22 SBA (in), 23 CBA (in), 24 VCC (power) hidden to VCC
1 alternate drawing of the same symbol

## SN74HC679
designator U?
12-BIT ADDRESS COMPARATORS
footprint SO20W
footprint DIP-20
pins: 1 A1 (in), 2 A2 (in), 3 A3 (in), 4 A4 (in), 5 A5 (in), 6 A6 (in), 7 A7 (in), 8 A8 (in), 9 A9 (in), 10 GND (power) hidden to GND, 11 A10 (in), 12 A11 (in), 13 A12 (in), 14 P0 (in), 15 P1 (in), 16 P2 (in), 17 P3 (in), 18 Y (out), 19 ~{G} (in), 20 VCC (power) hidden to VCC
1 alternate drawing of the same symbol

## SN74HC682
designator U?
8-BIT MAGNITUDE/IDENTITY COMPARATOR
footprint SO20W
footprint DIP-20
pins: 1 ~{P>Q} (out), 2 P0 (in), 3 Q0 (in), 4 P1 (in), 5 Q1 (in), 6 P2 (in), 7 Q2 (in), 8 P3 (in), 9 Q3 (in), 10 GND (power) hidden to GND, 11 P4 (in), 12 Q4 (in), 13 P5 (in), 14 Q5 (in), 15 P6 (in), 16 Q6 (in), 17 P7 (in), 18 Q7 (in), 19 ~{P=Q} (out), 20 VCC (power) hidden to VCC
1 alternate drawing of the same symbol

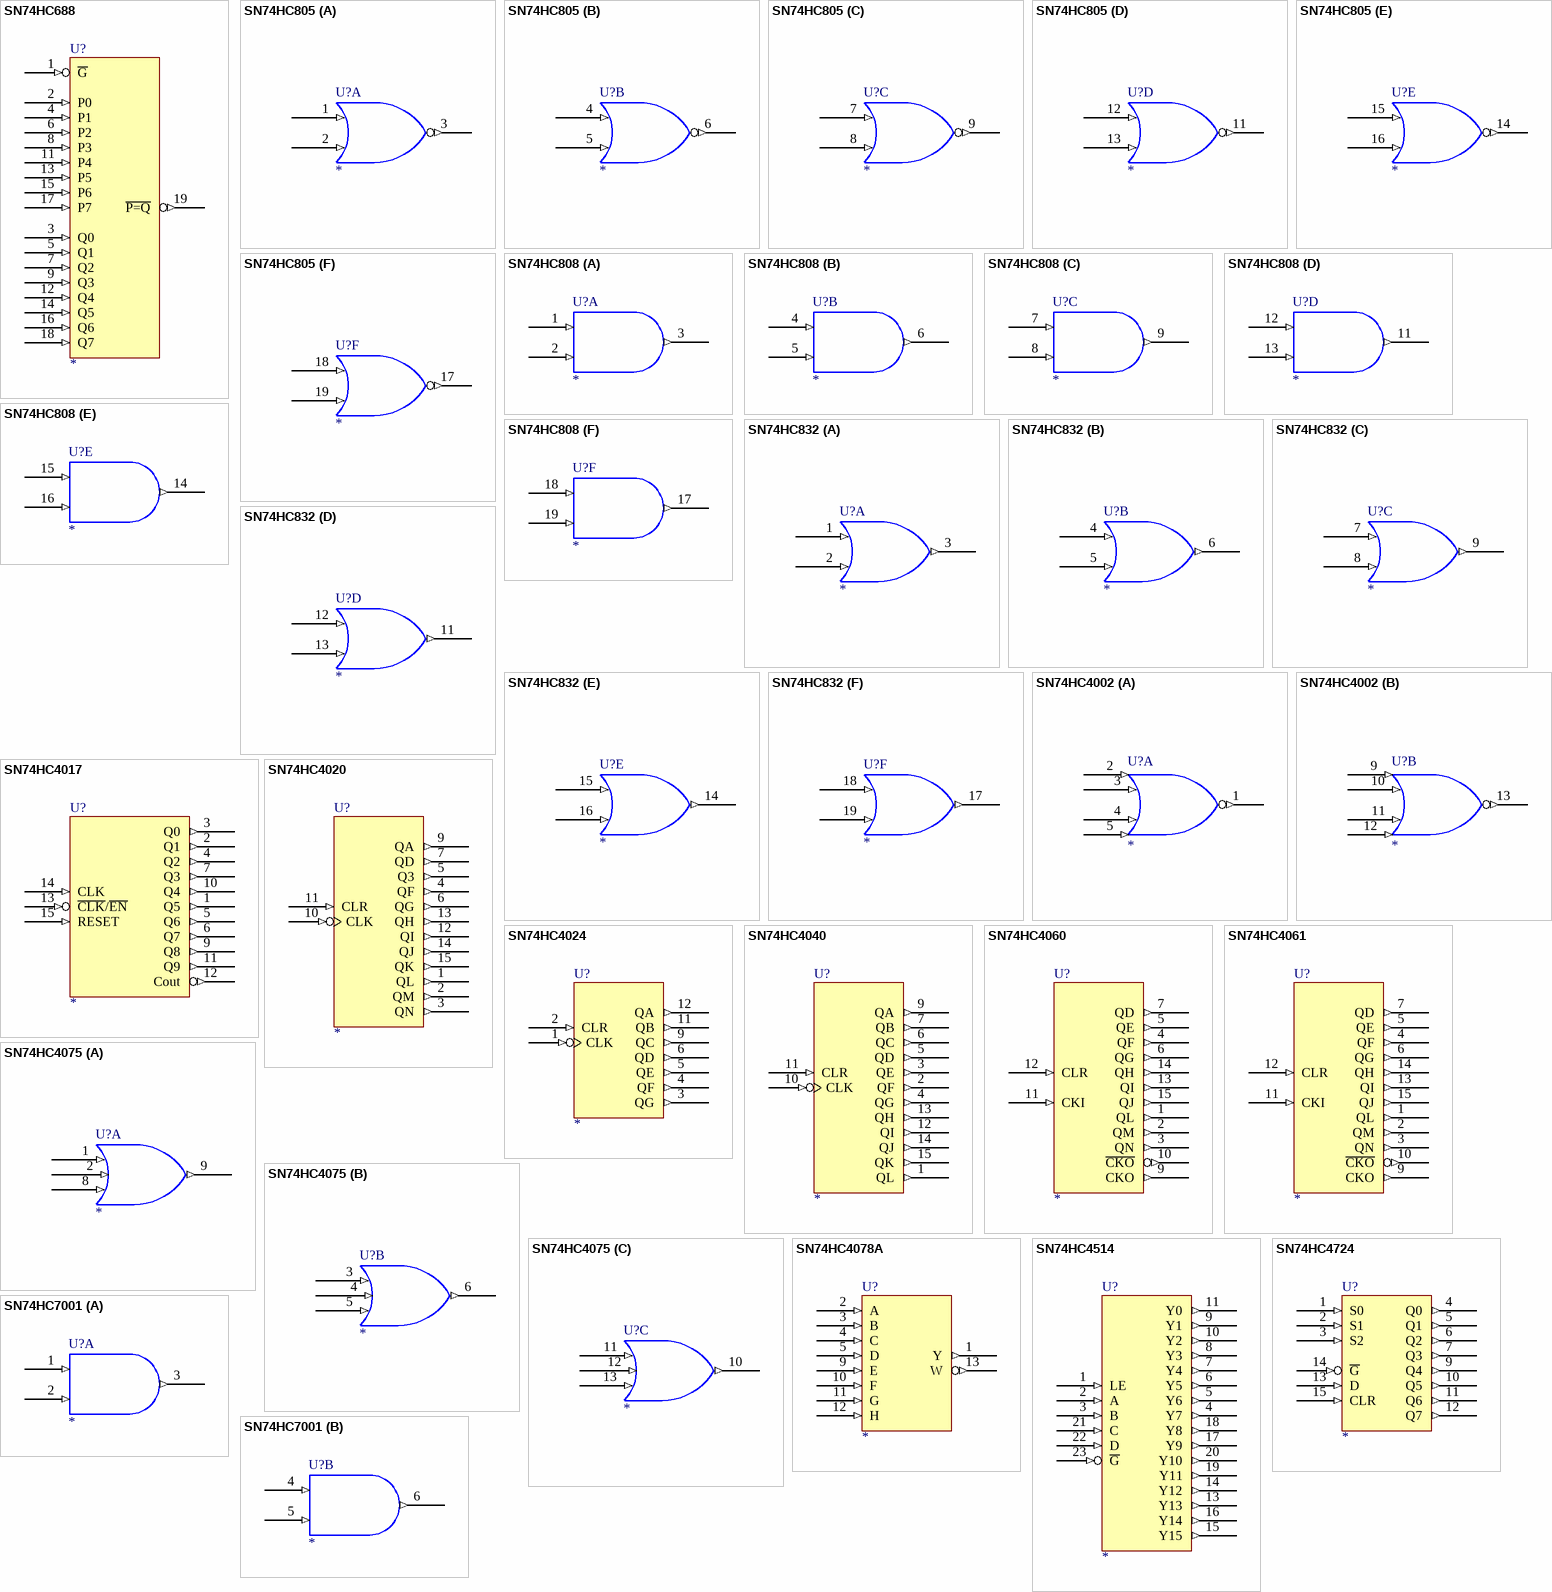
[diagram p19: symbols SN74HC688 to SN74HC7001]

## SN74HC688
designator U?
8-BIT IDENTITY COMPARATOR
footprint SO20W
footprint DIP-20
pins: 1 ~{G} (in), 2 P0 (in), 3 Q0 (in), 4 P1 (in), 5 Q1 (in), 6 P2 (in), 7 Q2 (in), 8 P3 (in), 9 Q3 (in), 10 GND (power) hidden to GND, 11 P4 (in), 12 Q4 (in), 13 P5 (in), 14 Q5 (in), 15 P6 (in), 16 Q6 (in), 17 P7 (in), 18 Q7 (in), 19 ~{P=Q} (out), 20 VCC (power) hidden to VCC
1 alternate drawing of the same symbol

## SN74HC805
designator U?
HEX 2-IN NOR DRIVERS
footprint SO20W
footprint DIP-20
part A pins: 1 (in), 2 (in), 3 (out), 10 GND (power) hidden to GND, 20 VCC (power) hidden to VCC
part B pins: 4 (in), 5 (in), 6 (out), 10 GND (power) hidden to GND, 20 VCC (power) hidden to VCC
part C pins: 7 (in), 8 (in), 9 (out), 10 GND (power) hidden to GND, 20 VCC (power) hidden to VCC
part D pins: 10 GND (power) hidden to GND, 11 (out), 12 (in), 13 (in), 20 VCC (power) hidden to VCC
part E pins: 10 GND (power) hidden to GND, 14 (out), 15 (in), 16 (in), 20 VCC (power) hidden to VCC
part F pins: 10 GND (power) hidden to GND, 17 (out), 18 (in), 19 (in), 20 VCC (power) hidden to VCC
2 alternate drawings of the same symbol

## SN74HC808
designator U?
HEX 2-IN AND DRIVERS
footprint SO20W
footprint DIP-20
part A pins: 1 (in), 2 (in), 3 (out), 10 GND (power) hidden to GND, 20 VCC (power) hidden to VCC
part B pins: 4 (in), 5 (in), 6 (out), 10 GND (power) hidden to GND, 20 VCC (power) hidden to VCC
part C pins: 7 (in), 8 (in), 9 (out), 10 GND (power) hidden to GND, 20 VCC (power) hidden to VCC
part D pins: 10 GND (power) hidden to GND, 11 (out), 12 (in), 13 (in), 20 VCC (power) hidden to VCC
part E pins: 10 GND (power) hidden to GND, 14 (out), 15 (in), 16 (in), 20 VCC (power) hidden to VCC
part F pins: 10 GND (power) hidden to GND, 17 (out), 18 (in), 19 (in), 20 VCC (power) hidden to VCC
2 alternate drawings of the same symbol

## SN74HC832
designator U?
HEX 2-IN OR DRIVERS
footprint SO20W
footprint DIP-20
part A pins: 1 (in), 2 (in), 3 (out), 10 GND (power) hidden to GND, 20 VCC (power) hidden to VCC
part B pins: 4 (in), 5 (in), 6 (out), 10 GND (power) hidden to GND, 20 VCC (power) hidden to VCC
part C pins: 7 (in), 8 (in), 9 (out), 10 GND (power) hidden to GND, 20 VCC (power) hidden to VCC
part D pins: 10 GND (power) hidden to GND, 11 (out), 12 (in), 13 (in), 20 VCC (power) hidden to VCC
part E pins: 10 GND (power) hidden to GND, 14 (out), 15 (in), 16 (in), 20 VCC (power) hidden to VCC
part F pins: 10 GND (power) hidden to GND, 17 (out), 18 (in), 19 (in), 20 VCC (power) hidden to VCC
2 alternate drawings of the same symbol

## SN74HC4002
designator U?
Dual 4-INPUT NOR GATE
footprint SO14
footprint DIP-14
part A pins: 1 (out), 2 (in), 3 (in), 4 (in), 5 (in), 7 GND (power) hidden to GND, 14 VCC (power) hidden to VCC
part B pins: 7 GND (power) hidden to GND, 9 (in), 10 (in), 11 (in), 12 (in), 13 (out), 14 VCC (power) hidden to VCC
2 alternate drawings of the same symbol

## SN74HC4017
designator U?
DECADE COUNTER/DIVIDER
footprint DIP-16
pins: 1 Q5 (out), 2 Q1 (out), 3 Q0 (out), 4 Q2 (out), 5 Q6 (out), 6 Q7 (out), 7 Q3 (out), 8 GND (power) hidden to GND, 9 Q8 (out), 10 Q4 (out), 11 Q9 (out), 12 Cout (out), 13 ~{CLK}/~{EN} (in), 14 CLK (in), 15 RESET (in), 16 VCC (power) hidden to VCC
1 alternate drawing of the same symbol

## SN74HC4020
designator U?
14-BIT BINARY COUNTER
footprint SO16
footprint DIP-16
pins: 1 QL (out), 2 QM (out), 3 QN (out), 4 QF (out), 5 Q3 (out), 6 QG (out), 7 QD (out), 8 GND (power) hidden to GND, 9 QA (out), 10 CLK (in), 11 CLR (in), 12 QI (out), 13 QH (out), 14 QJ (out), 15 QK (out), 16 VCC (power) hidden to VCC
1 alternate drawing of the same symbol

## SN74HC4024
designator U?
ASYNCHRONOUS 7-BIT BINARY COUNTERS
footprint SO14
footprint DIP-14
pins: 1 CLK (in), 2 CLR (in), 3 QG (out), 4 QF (out), 5 QE (out), 6 QD (out), 7 GND (power) hidden to GND, 9 QC (out), 11 QB (out), 12 QA (out), 14 VCC (power) hidden to VCC
1 alternate drawing of the same symbol

## SN74HC4040
designator U?
ASYNCHRONOUS 12-BIT BINARY COUNTERS
footprint SO16
footprint DIP-16
pins: 1 QL (out), 2 QF (out), 3 QE (out), 4 QG (out), 5 QD (out), 6 QC (out), 7 QB (out), 8 GND (power) hidden to GND, 9 QA (out), 10 CLK (in), 11 CLR (in), 12 QI (out), 13 QH (out), 14 QJ (out), 15 QK (out), 16 VCC (power) hidden to VCC
1 alternate drawing of the same symbol

## SN74HC4060
designator U?
ASYNCHRONOUS 14-STAGE BINARY COUNTERS AND OSCILATORS
footprint SO16
footprint DIP-16
pins: 1 QL (out), 2 QM (out), 3 QN (out), 4 QF (out), 5 QE (out), 6 QG (out), 7 QD (out), 8 GND (power) hidden to GND, 9 CKO (out), 10 ~{CKO} (out), 11 CKI (in), 12 CLR (in), 13 QI (out), 14 QH (out), 15 QJ (out), 16 VCC (power) hidden to VCC
1 alternate drawing of the same symbol

## SN74HC4061
designator U?
ASYNCHRONOUS 14-STAGE BINARY COUNTERS AND OSCILATORS
footprint SO16
footprint DIP-16
pins: 1 QL (out), 2 QM (out), 3 QN (out), 4 QF (out), 5 QE (out), 6 QG (out), 7 QD (out), 8 GND (power) hidden to GND, 9 CKO (out), 10 ~{CKO} (out), 11 CKI (in), 12 CLR (in), 13 QI (out), 14 QH (out), 15 QJ (out), 16 VCC (power) hidden to VCC
1 alternate drawing of the same symbol

## SN74HC4075
designator U?
TRIPLE 3-INPUT OR GATE
footprint SO14
footprint DIP-14
part A pins: 1 (in), 2 (in), 7 GND (power) hidden to GND, 8 (in), 9 (out), 14 VCC (power) hidden to VCC
part B pins: 3 (in), 4 (in), 5 (in), 6 (out), 7 GND (power) hidden to GND, 14 VCC (power) hidden to VCC
part C pins: 7 GND (power) hidden to GND, 10 (out), 11 (in), 12 (in), 13 (in), 14 VCC (power) hidden to VCC
2 alternate drawings of the same symbol

## SN74HC4078A
designator U?
8-INPUT OR/NOR GATE
footprint SO14
footprint DIP-14
pins: 1 Y (out), 2 A (in), 3 B (in), 4 C (in), 5 D (in), 7 GND (power) hidden to GND, 9 E (in), 10 F (in), 11 G (in), 12 H (in), 13 W (out), 14 VCC (power) hidden to VCC
1 alternate drawing of the same symbol

## SN74HC4514
designator U?
4-LINE TO 16-LINE DECODER/DEMULTIPLEXERS WITH ADDRESS LATCHES
footprint SO24W
footprint DIP-24
pins: 1 LE (in), 2 A (in), 3 B (in), 4 Y7 (out), 5 Y6 (out), 6 Y5 (out), 7 Y4 (out), 8 Y3 (out), 9 Y1 (out), 10 Y2 (out), 11 Y0 (out), 12 GND (power) hidden to GND, 13 Y13 (out), 14 Y12 (out), 15 Y15 (out), 16 Y14 (out), 17 Y9 (out), 18 Y8 (out), 19 Y11 (out), 20 Y10 (out), 21 C (in), 22 D (in), 23 ~{G} (in), 24 VCC (power) hidden to VCC
1 alternate drawing of the same symbol

## SN74HC4724
designator U?
8-BIT ADDRESSABLE LARCHES
footprint DIP-16
pins: 1 S0 (in), 2 S1 (in), 3 S2 (in), 4 Q0 (out), 5 Q1 (out), 6 Q2 (out), 7 Q3 (out), 8 GND (power) hidden to GND, 9 Q4 (out), 10 Q5 (out), 11 Q6 (out), 12 Q7 (out), 13 D (in), 14 ~{G} (in), 15 CLR (in), 16 VCC (power) hidden to VCC
1 alternate drawing of the same symbol

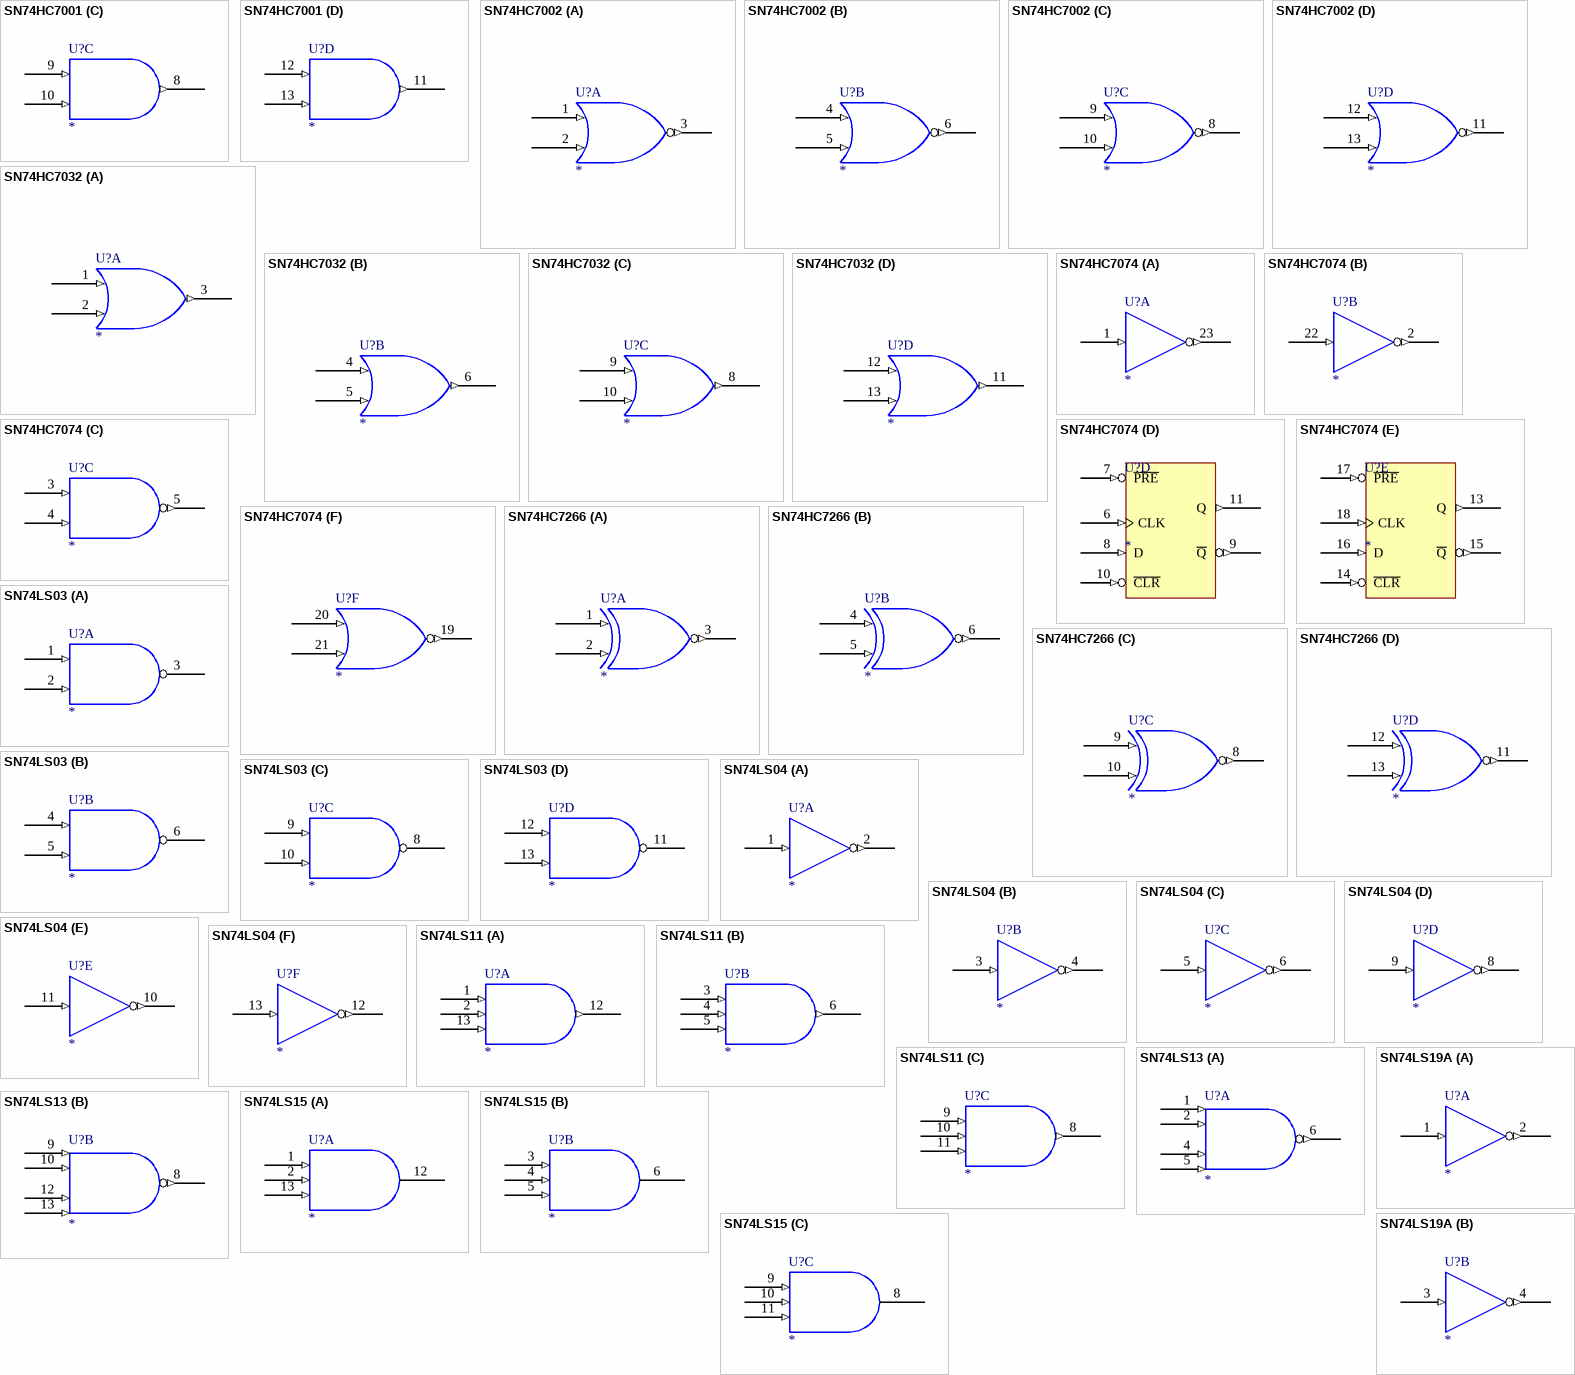
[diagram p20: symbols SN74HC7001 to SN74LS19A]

## SN74HC7001
designator U?
Quad 2-IN Pos AND G SCH INPUTS
footprint SO14
footprint DIP-14
part A pins: 1 (in), 2 (in), 3 (out), 7 GND (power) hidden to GND, 14 VCC (power) hidden to VCC
part B pins: 4 (in), 5 (in), 6 (out), 7 GND (power) hidden to GND, 14 VCC (power) hidden to VCC
part C pins: 7 GND (power) hidden to GND, 8 (out), 9 (in), 10 (in), 14 VCC (power) hidden to VCC
part D pins: 7 GND (power) hidden to GND, 11 (out), 12 (in), 13 (in), 14 VCC (power) hidden to VCC
2 alternate drawings of the same symbol

## SN74HC7002
designator U?
Quad 2-IN Pos NOR G SCH INPUTS
footprint SO14
footprint DIP-14
part A pins: 1 (in), 2 (in), 3 (out), 7 GND (power) hidden to GND, 14 VCC (power) hidden to VCC
part B pins: 4 (in), 5 (in), 6 (out), 7 GND (power) hidden to GND, 14 VCC (power) hidden to VCC
part C pins: 7 GND (power) hidden to GND, 8 (out), 9 (in), 10 (in), 14 VCC (power) hidden to VCC
part D pins: 7 GND (power) hidden to GND, 11 (out), 12 (in), 13 (in), 14 VCC (power) hidden to VCC
2 alternate drawings of the same symbol

## SN74HC7032
designator U?
Quad 2-IN Pos OR G SCH INPUTS
footprint SO14
footprint DIP-14
part A pins: 1 (in), 2 (in), 3 (out), 7 GND (power) hidden to GND, 14 VCC (power) hidden to VCC
part B pins: 4 (in), 5 (in), 6 (out), 7 GND (power) hidden to GND, 14 VCC (power) hidden to VCC
part C pins: 7 GND (power) hidden to GND, 8 (out), 9 (in), 10 (in), 14 VCC (power) hidden to VCC
part D pins: 7 GND (power) hidden to GND, 11 (out), 12 (in), 13 (in), 14 VCC (power) hidden to VCC
2 alternate drawings of the same symbol

## SN74HC7074
designator U?
6-SECTION MULTIFUNCTION NAND INVERT NOR FF
footprint SO24W
footprint DIP-24
part A pins: 1 (in), 12 GND (power) hidden to GND, 23 (out), 24 VCC (power) hidden to VCC
part B pins: 2 (out), 12 GND (power) hidden to GND, 22 (in), 24 VCC (power) hidden to VCC
part C pins: 3 (in), 4 (in), 5 (out), 12 GND (power) hidden to GND, 24 VCC (power) hidden to VCC
part D pins: 6 CLK (in), 7 ~{PRE} (in), 8 D (in), 9 ~{Q} (out), 10 ~{CLR} (in), 11 Q (out), 12 GND (power) hidden to GND, 24 VCC (power) hidden to VCC
part E pins: 12 GND (power) hidden to GND, 13 Q (out), 14 ~{CLR} (in), 15 ~{Q} (out), 16 D (in), 17 ~{PRE} (in), 18 CLK (in), 24 VCC (power) hidden to VCC
part F pins: 12 GND (power) hidden to GND, 19 (out), 20 (in), 21 (in), 24 VCC (power) hidden to VCC
2 alternate drawings of the same symbol

## SN74HC7266
designator U?
QUAD 2-IN XNOR G
footprint SO14
footprint DIP-14
part A pins: 1 (in), 2 (in), 3 (out), 7 GND (power) hidden to GND, 14 VCC (power) hidden to VCC
part B pins: 4 (in), 5 (in), 6 (out), 7 GND (power) hidden to GND, 14 VCC (power) hidden to VCC
part C pins: 7 GND (power) hidden to GND, 8 (out), 9 (in), 10 (in), 14 VCC (power) hidden to VCC
part D pins: 7 GND (power) hidden to GND, 11 (out), 12 (in), 13 (in), 14 VCC (power) hidden to VCC
1 alternate drawing of the same symbol

## SN74LS03
designator U?
Quad 2-IN Pos Nand G OCO
footprint SO14
footprint DIP-14
part A pins: 1 (in), 2 (in), 3 (oc), 7 GND (power) hidden to GND, 14 VCC (power) hidden to VCC
part B pins: 4 (in), 5 (in), 6 (oc), 7 GND (power) hidden to GND, 14 VCC (power) hidden to VCC
part C pins: 7 GND (power) hidden to GND, 8 (oc), 9 (in), 10 (in), 14 VCC (power) hidden to VCC
part D pins: 7 GND (power) hidden to GND, 11 (oc), 12 (in), 13 (in), 14 VCC (power) hidden to VCC
2 alternate drawings of the same symbol

## SN74LS04
designator U?
Hex Inverters
footprint SO14
footprint DIP-14
part A pins: 1 (in), 2 (out), 7 GND (power) hidden to GND, 14 VCC (power) hidden to VCC
part B pins: 3 (in), 4 (out), 7 GND (power) hidden to GND, 14 VCC (power) hidden to VCC
part C pins: 5 (in), 6 (out), 7 GND (power) hidden to GND, 14 VCC (power) hidden to VCC
part D pins: 7 GND (power) hidden to GND, 8 (out), 9 (in), 14 VCC (power) hidden to VCC
part E pins: 7 GND (power) hidden to GND, 10 (out), 11 (in), 14 VCC (power) hidden to VCC
part F pins: 7 GND (power) hidden to GND, 12 (out), 13 (in), 14 VCC (power) hidden to VCC
2 alternate drawings of the same symbol

## SN74LS11
designator U?
Triple 3-IN Pos And G
footprint SO14
footprint DIP-14
part A pins: 1 (in), 2 (in), 7 GND (power) hidden to GND, 12 (out), 13 (in), 14 VCC (power) hidden to VCC
part B pins: 3 (in), 4 (in), 5 (in), 6 (out), 7 GND (power) hidden to GND, 14 VCC (power) hidden to VCC
part C pins: 7 GND (power) hidden to GND, 8 (out), 9 (in), 10 (in), 11 (in), 14 VCC (power) hidden to VCC
2 alternate drawings of the same symbol

## SN74LS13
designator U?
Dual 4-IN Pos Nand G SCH
footprint SO14
footprint DIP-14
part A pins: 1 (in), 2 (in), 4 (in), 5 (in), 6 (out), 7 GND (power) hidden to GND, 14 VCC (power) hidden to VCC
part B pins: 7 GND (power) hidden to GND, 8 (out), 9 (in), 10 (in), 12 (in), 13 (in), 14 VCC (power) hidden to VCC
2 alternate drawings of the same symbol

## SN74LS15
designator U?
Triple 3-IN Pos And G OCO
footprint SO14
footprint DIP-14
part A pins: 1 (in), 2 (in), 7 GND (power) hidden to GND, 12 (oc), 13 (in), 14 VCC (power) hidden to VCC
part B pins: 3 (in), 4 (in), 5 (in), 6 (oc), 7 GND (power) hidden to GND, 14 VCC (power) hidden to VCC
part C pins: 7 GND (power) hidden to GND, 8 (oc), 9 (in), 10 (in), 11 (in), 14 VCC (power) hidden to VCC
2 alternate drawings of the same symbol

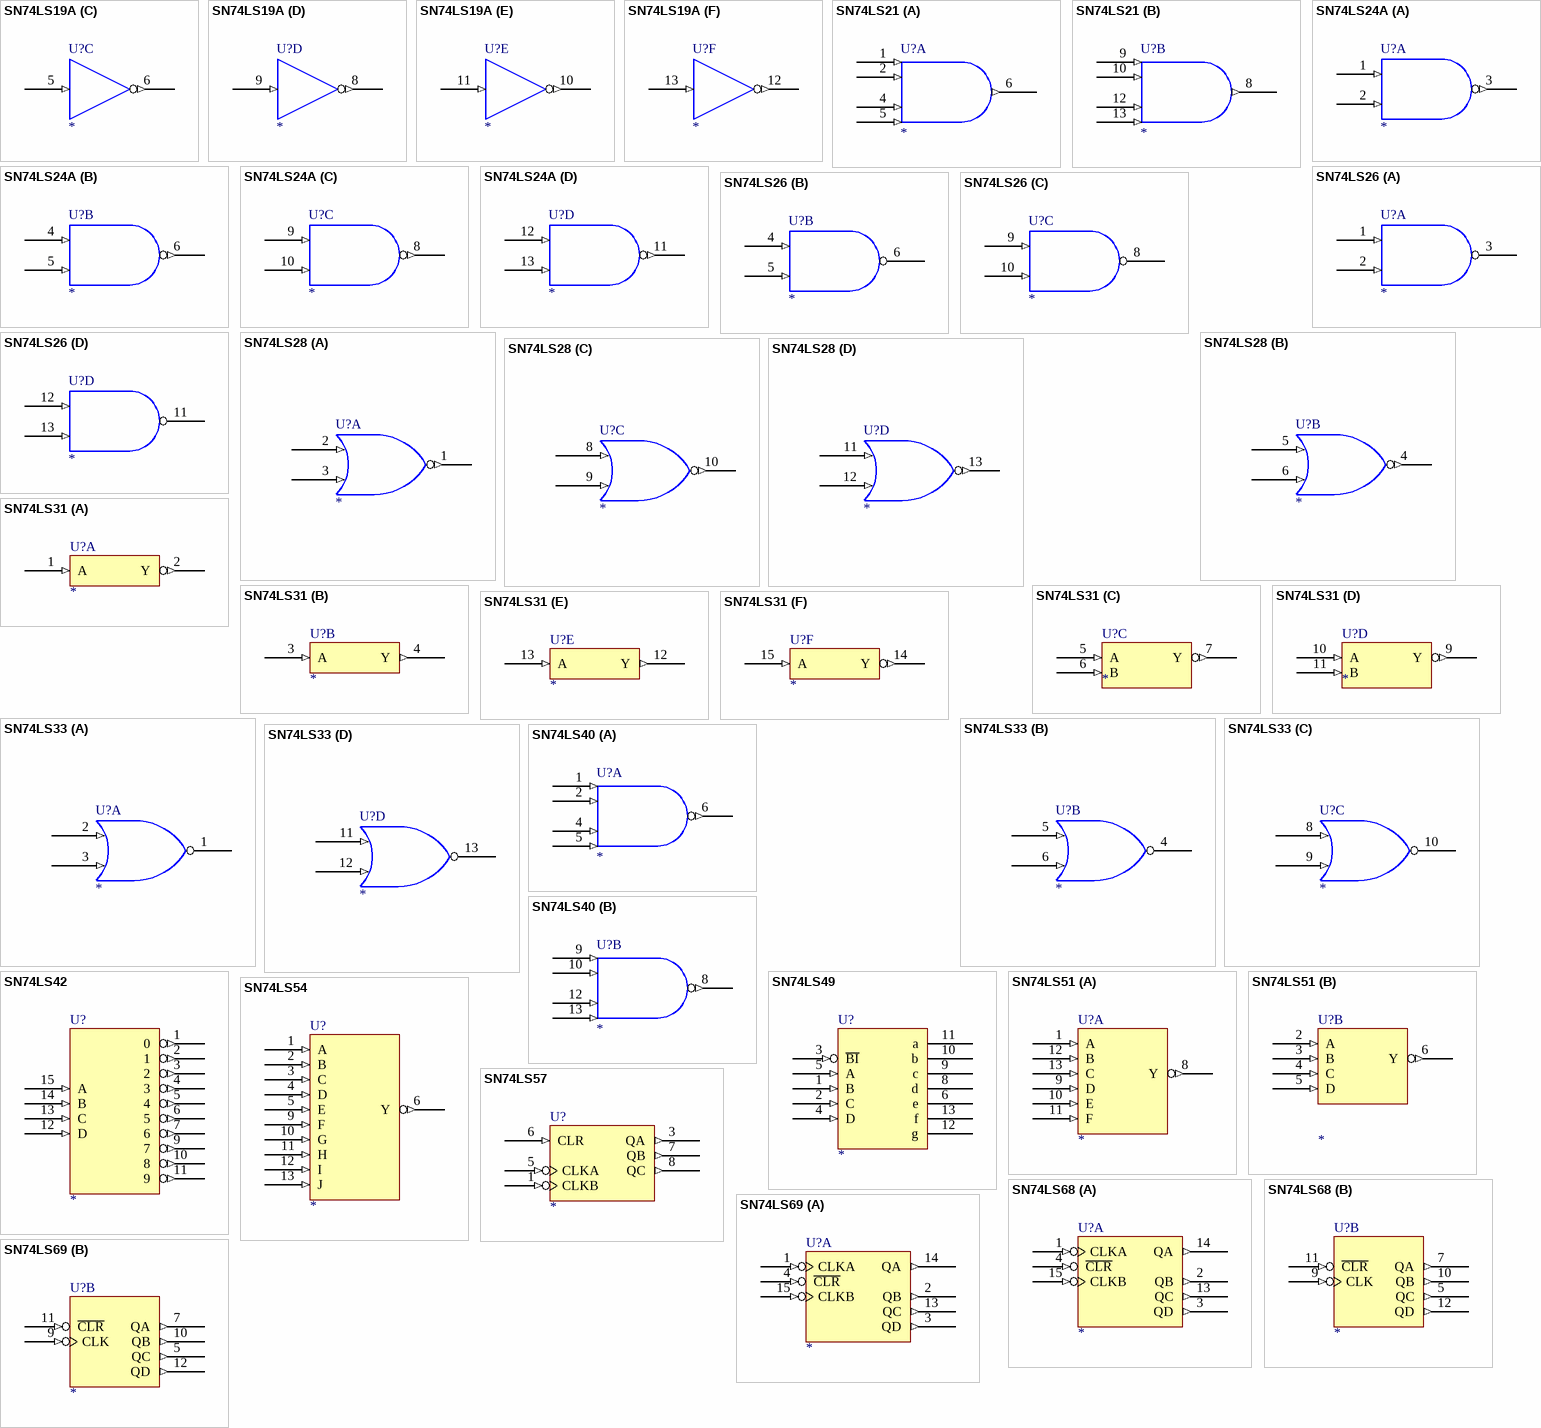
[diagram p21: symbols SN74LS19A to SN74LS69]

## SN74LS19A
designator U?
Hex Inverter Totem
footprint SO14
footprint DIP-14
part A pins: 1 (in), 2 (out), 7 GND (power) hidden to GND, 14 VCC (power) hidden to VCC
part B pins: 3 (in), 4 (out), 7 GND (power) hidden to GND, 14 VCC (power) hidden to VCC
part C pins: 5 (in), 6 (out), 7 GND (power) hidden to GND, 14 VCC (power) hidden to VCC
part D pins: 7 GND (power) hidden to GND, 8 (out), 9 (in), 14 VCC (power) hidden to VCC
part E pins: 7 GND (power) hidden to GND, 10 (out), 11 (in), 14 VCC (power) hidden to VCC
part F pins: 7 GND (power) hidden to GND, 12 (out), 13 (in), 14 VCC (power) hidden to VCC
2 alternate drawings of the same symbol

## SN74LS21
designator U?
Dual 4-IN Pos And G
footprint SO14
footprint DIP-14
part A pins: 1 (in), 2 (in), 4 (in), 5 (in), 6 (out), 7 GND (power) hidden to GND, 14 VCC (power) hidden to VCC
part B pins: 7 GND (power) hidden to GND, 8 (out), 9 (in), 10 (in), 12 (in), 13 (in), 14 VCC (power) hidden to VCC
2 alternate drawings of the same symbol

## SN74LS24A
designator U?
Quad 2-IN Pos Nand G SCH totem
footprint SO14
footprint DIP-14
part A pins: 1 (in), 2 (in), 3 (out), 7 GND (power) hidden to GND, 14 VCC (power) hidden to VCC
part B pins: 4 (in), 5 (in), 6 (out), 7 GND (power) hidden to GND, 14 VCC (power) hidden to VCC
part C pins: 7 GND (power) hidden to GND, 8 (out), 9 (in), 10 (in), 14 VCC (power) hidden to VCC
part D pins: 7 GND (power) hidden to GND, 11 (out), 12 (in), 13 (in), 14 VCC (power) hidden to VCC
2 alternate drawings of the same symbol

## SN74LS26
designator U?
Quad 2-IN Pos Nand G HV INTF
footprint SO14
footprint DIP-14
part A pins: 1 (in), 2 (in), 3 (oc), 7 GND (power) hidden to GND, 14 VCC (power) hidden to VCC
part B pins: 4 (in), 5 (in), 6 (oc), 7 GND (power) hidden to GND, 14 VCC (power) hidden to VCC
part C pins: 7 GND (power) hidden to GND, 8 (oc), 9 (in), 10 (in), 14 VCC (power) hidden to VCC
part D pins: 7 GND (power) hidden to GND, 11 (oc), 12 (in), 13 (in), 14 VCC (power) hidden to VCC
2 alternate drawings of the same symbol

## SN74LS28
designator U?
Quad 2-IN Pos Nor G BUF
footprint SO14
footprint DIP-14
part A pins: 1 (out), 2 (in), 3 (in), 7 GND (power) hidden to GND, 14 VCC (power) hidden to VCC
part B pins: 4 (out), 5 (in), 6 (in), 7 GND (power) hidden to GND, 14 VCC (power) hidden to VCC
part C pins: 7 GND (power) hidden to GND, 8 (in), 9 (in), 10 (out), 14 VCC (power) hidden to VCC
part D pins: 7 GND (power) hidden to GND, 11 (in), 12 (in), 13 (out), 14 VCC (power) hidden to VCC
2 alternate drawings of the same symbol

## SN74LS31
designator U?
Delay Elements
footprint SO16
footprint DIP-16
part A pins: 1 A (in), 2 Y (out), 8 GND (power) hidden to GND, 16 VCC (power) hidden to VCC
part B pins: 3 A (in), 4 Y (out), 8 GND (power) hidden to GND, 16 VCC (power) hidden to VCC
part C pins: 5 A (in), 6 B (in), 7 Y (out), 8 GND (power) hidden to GND, 16 VCC (power) hidden to VCC
part D pins: 8 GND (power) hidden to GND, 9 Y (out), 10 A (in), 11 B (in), 16 VCC (power) hidden to VCC
part E pins: 8 GND (power) hidden to GND, 12 Y (out), 13 A (in), 16 VCC (power) hidden to VCC
part F pins: 8 GND (power) hidden to GND, 14 Y (out), 15 A (in), 16 VCC (power) hidden to VCC
1 alternate drawing of the same symbol

## SN74LS33
designator U?
Quad 2-IN Pos Nor G BUF OCO
footprint SO14
footprint DIP-14
part A pins: 1 (oc), 2 (in), 3 (in), 7 GND (power) hidden to GND, 14 VCC (power) hidden to VCC
part B pins: 4 (oc), 5 (in), 6 (in), 7 GND (power) hidden to GND, 14 VCC (power) hidden to VCC
part C pins: 7 GND (power) hidden to GND, 8 (in), 9 (in), 10 (oc), 14 VCC (power) hidden to VCC
part D pins: 7 GND (power) hidden to GND, 11 (in), 12 (in), 13 (oc), 14 VCC (power) hidden to VCC
2 alternate drawings of the same symbol

## SN74LS40
designator U?
Dual 4-in Pos Nand G BUF
footprint SO14
footprint DIP-14
part A pins: 1 (in), 2 (in), 4 (in), 5 (in), 6 (out), 7 GND (power) hidden to GND, 14 VCC (power) hidden to VCC
part B pins: 7 GND (power) hidden to GND, 8 (out), 9 (in), 10 (in), 12 (in), 13 (in), 14 VCC (power) hidden to VCC
2 alternate drawings of the same symbol

## SN74LS42
designator U?
4-line BCD to 10-line decimal Dec
footprint SO16
footprint DIP-16
pins: 1 0 (out), 2 1 (out), 3 2 (out), 4 3 (out), 5 4 (out), 6 5 (out), 7 6 (out), 8 GND (power) hidden to GND, 9 7 (out), 10 8 (out), 11 9 (out), 12 D (in), 13 C (in), 14 B (in), 15 A (in), 16 VCC (power) hidden to VCC
1 alternate drawing of the same symbol

## SN74LS49
designator U?
BCD-To-SEVEN-SEGMENT DEC DRV
footprint SO14
footprint DIP-14
pins: 1 B (in), 2 C (in), 3 ~{BI} (in), 4 D (in), 5 A (in), 6 e (oc), 7 GND (power) hidden to GND, 8 d (oc), 9 c (oc), 10 b (oc), 11 a (oc), 12 g (oc), 13 f (oc), 14 VCC (power) hidden to VCC
1 alternate drawing of the same symbol

## SN74LS51
designator U?
DUAL 2-WIDE 2&3-IN AND-OR-INVERT G
footprint SO14
footprint DIP-14
part A pins: 1 A (in), 7 GND (power) hidden to GND, 8 Y (out), 9 D (in), 10 E (in), 11 F (in), 12 B (in), 13 C (in), 14 VCC (power) hidden to VCC
part B pins: 2 A (in), 3 B (in), 4 C (in), 5 D (in), 6 Y (out), 7 GND (power) hidden to GND, 14 VCC (power) hidden to VCC
1 alternate drawing of the same symbol

## SN74LS54
designator U?
4-WIDE 2-IN AND-OR-INVERT G
footprint SO14
footprint DIP-14
pins: 1 A (in), 2 B (in), 3 C (in), 4 D (in), 5 E (in), 6 Y (out), 7 GND (power) hidden to GND, 9 F (in), 10 G (in), 11 H (in), 12 I (in), 13 J (in), 14 VCC (power) hidden to VCC
1 alternate drawing of the same symbol

## SN74LS57
designator U?
FREQUENCY DIVIDERS
footprint DIP-8
pins: 1 CLKB (in), 2 VCC (power) hidden to VCC, 3 QA (out), 4 GND (power) hidden to GND, 5 CLKA (in), 6 CLR (in), 7 QB (out), 8 QC (out)
1 alternate drawing of the same symbol

## SN74LS68
designator U?
DUAL 4-BIT DECADE OR BINARY CNT
footprint SO16
footprint DIP-16
part A pins: 1 CLKA (in), 2 QB (out), 3 QD (out), 4 ~{CLR} (in), 8 GND (power) hidden to GND, 13 QC (out), 14 QA (out), 15 CLKB (in), 16 VCC (power) hidden to VCC
part B pins: 5 QC (out), 7 QA (out), 8 GND (power) hidden to GND, 9 CLK (in), 10 QB (out), 11 ~{CLR} (in), 12 QD (out), 16 VCC (power) hidden to VCC
1 alternate drawing of the same symbol

## SN74LS69
designator U?
DUAL 4-BIT DECADE OR BINARY CNT
footprint SO16
footprint DIP-16
part A pins: 1 CLKA (in), 2 QB (out), 3 QD (out), 4 ~{CLR} (in), 8 GND (power) hidden to GND, 13 QC (out), 14 QA (out), 15 CLKB (in), 16 VCC (power) hidden to VCC
part B pins: 5 QC (out), 7 QA (out), 8 GND (power) hidden to GND, 9 CLK (in), 10 QB (out), 11 ~{CLR} (in), 12 QD (out), 16 VCC (power) hidden to VCC
1 alternate drawing of the same symbol

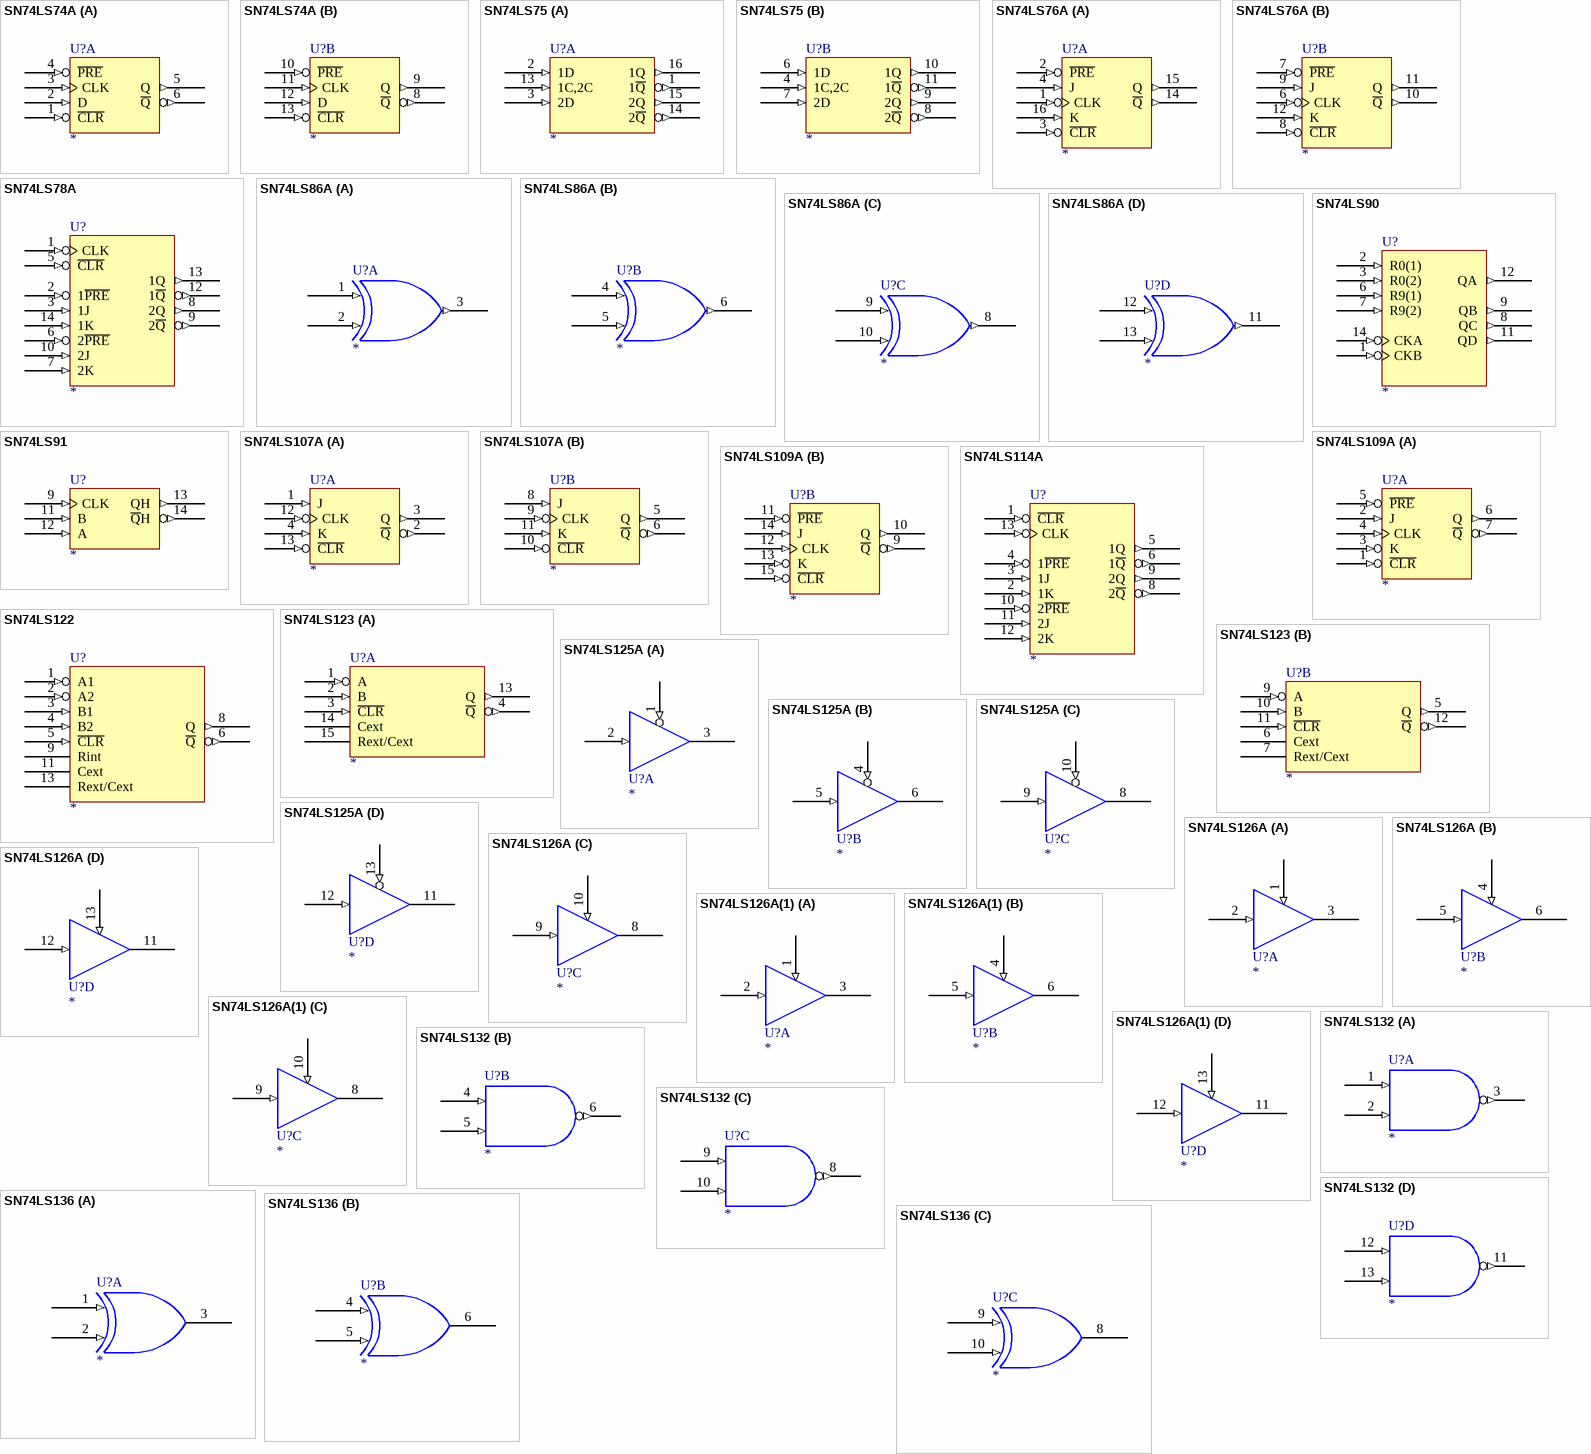
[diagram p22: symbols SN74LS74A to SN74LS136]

## SN74LS74A
designator U?
DUAL D PET FF RS CR
footprint SO14
footprint DIP-14
part A pins: 1 ~{CLR} (in), 2 D (in), 3 CLK (in), 4 ~{PRE} (in), 5 Q (out), 6 ~{Q} (out), 7 GND (power) hidden to GND, 14 VCC (power) hidden to VCC
part B pins: 7 GND (power) hidden to GND, 8 ~{Q} (out), 9 Q (out), 10 ~{PRE} (in), 11 CLK (in), 12 D (in), 13 ~{CLR} (in), 14 VCC (power) hidden to VCC
1 alternate drawing of the same symbol

## SN74LS75
designator U?
4-BIT BISTABLE LCH
footprint SO16
footprint DIP-16
part A pins: 1 1~{Q} (out), 2 1D (in), 3 2D (in), 5 VCC (power) hidden to VCC, 12 GND (power) hidden to GND, 13 1C,2C (in), 14 2~{Q} (out), 15 2Q (out), 16 1Q (out)
part B pins: 4 1C,2C (in), 5 VCC (power) hidden to VCC, 6 1D (in), 7 2D (in), 8 2~{Q} (out), 9 2Q (out), 10 1Q (out), 11 1~{Q} (out), 12 GND (power) hidden to GND
1 alternate drawing of the same symbol

## SN74LS76A
designator U?
DUAL J-K NET FF RS CR
footprint SO16
footprint DIP-16
part A pins: 1 CLK (in), 2 ~{PRE} (in), 3 ~{CLR} (in), 4 J (in), 5 VCC (power) hidden to VCC, 13 GND (power) hidden to GND, 14 ~{Q} (out), 15 Q (out), 16 K (in)
part B pins: 5 VCC (power) hidden to VCC, 6 CLK (in), 7 ~{PRE} (in), 8 ~{CLR} (in), 9 J (in), 10 ~{Q} (out), 11 Q (out), 12 K (in), 13 GND (power) hidden to GND
1 alternate drawing of the same symbol

## SN74LS78A
designator U?
DUAL J-K FF RS COM CLK COM CR
footprint SO14
footprint DIP-14
pins: 1 CLK (in), 2 1~{PRE} (in), 3 1J (in), 4 VCC (power) hidden to VCC, 5 ~{CLR} (in), 6 2~{PRE} (in), 7 2K (in), 8 2Q (out), 9 2~{Q} (out), 10 2J (in), 11 GND (power) hidden to GND, 12 1~{Q} (out), 13 1Q (out), 14 1K (in)
1 alternate drawing of the same symbol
